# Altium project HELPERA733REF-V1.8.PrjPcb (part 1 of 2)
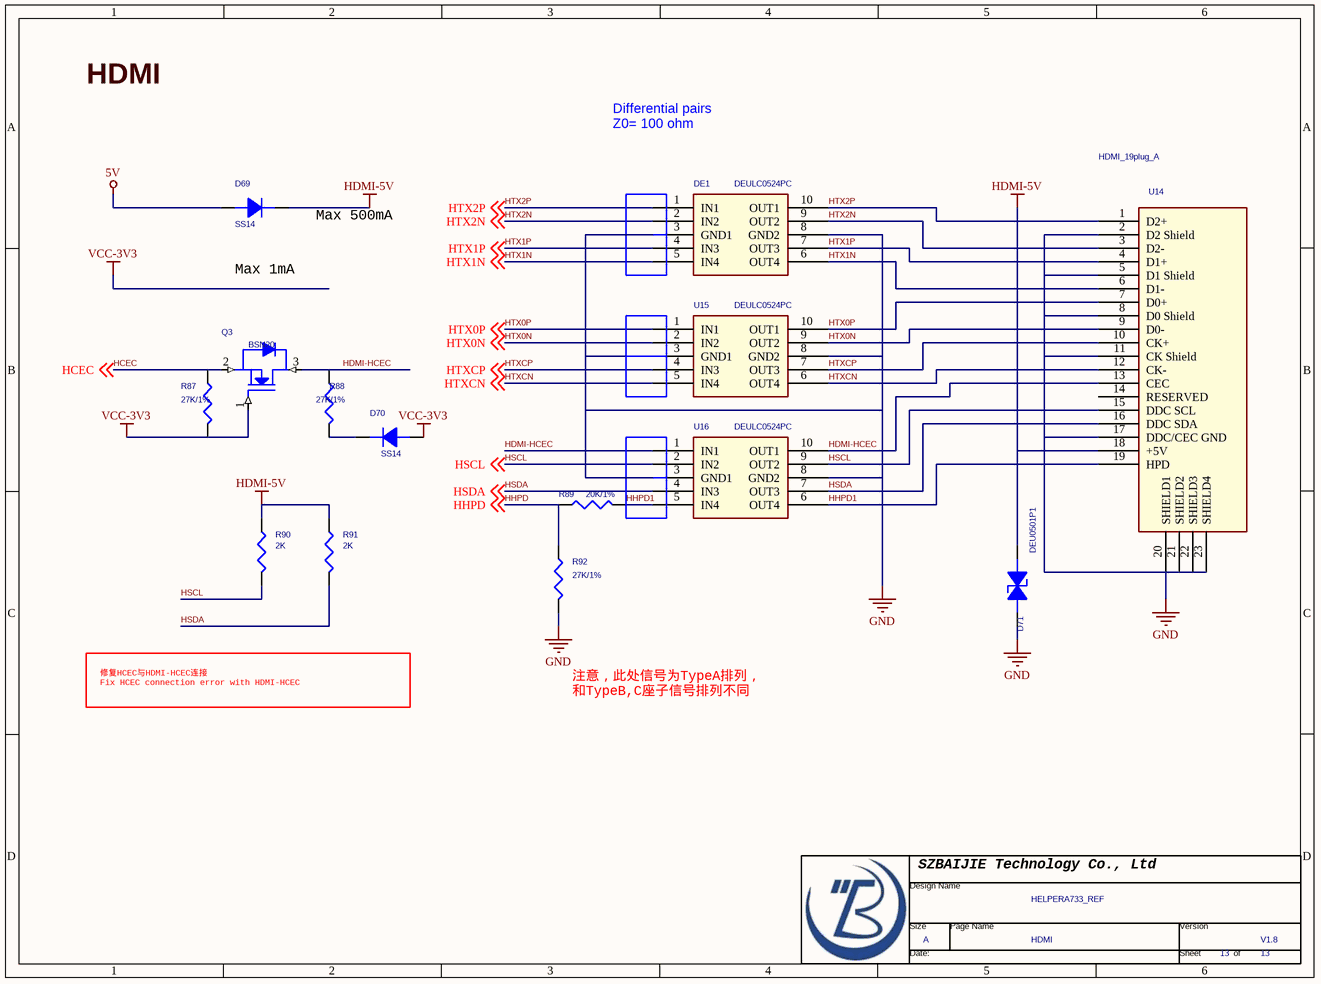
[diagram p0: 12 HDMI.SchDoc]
13 sheets, 488 parts. Net scope: global (net labels, ports and power ports of the same name join across sheets).
Sheets:
  12 HDMI.SchDoc
  11 OTG_host_HUB.SchDoc
  10 Ethernet.SchDoc
  09 IO_ADC_BEEP.SchDoc
  08  UART_485.SchDoc
  07 M.SchDoc
  06 AUDIO AC101_AC101B.SchDoc
  05 TF_KEY_RTC.SchDoc
  04 LCD.SchDoc
  03 CAMERA.SchDoc
  02 Power.SchDoc
  01 CORE.SchDoc
  00 Change log.SchDoc

## Sheet 12 HDMI.SchDoc
size 246 x 182 mm

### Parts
(Parts that share a designator on the sheet are numbered #1, #2 ... from top to bottom, then left to right.)
*#1  Page Count: 13  Page Size: A  Title: HELPERA733_REF  RevCode: V1.8  Doc: HDMI  (hidden comment: TitleBlock0-BJ)  (graphical)
D69  SS14  [SOD123]
D70  SS14  [SOD123]
D71  DEU0501P1  [ESD0402]
DE1  DEULC0524PC  [DFN2510-10_L2.5-W1.0-P0.50-BL]
Q3  BSN20  [sot-23]
R87  27K/1%  [R0402]
R88  27K/1%  [R0402]
R89  20K/1%  [R0402]
R90  2K  [R0402]
R91  2K  [R0402]
R92  27K/1%  [R0402]
U14  HDMI_19plug_A  [HDMIQ]
U15  DEULC0524PC  [DFN2510-10_L2.5-W1.0-P0.50-BL]
U16  DEULC0524PC  [DFN2510-10_L2.5-W1.0-P0.50-BL]

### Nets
5V: D69.1
GND: D71.2(CATHODE) DE1.3(GND1) DE1.8(GND2) R92.2 U14.2(D2_Shield) U14.5(D1_Shield) U14.8(D0_Shield) U14.11(CK_Shield) U14.17(DDC/CEC_GND) U14.20(SHIELD1) U14.21(SHIELD2) U14.22(SHIELD3) U14.23(SHIELD4) U15.3(GND1) U15.8(GND2) U16.3(GND1) U16.8(GND2)
HDMI-5V: D69.2 D71.1(ANODE) R90.2 R91.2 U14.18(+5V)
VCC-3V3: D70.1 Q3.1(GATE) R87.2
HCEC: Q3.2(SOURCE) R87.1 ; off-sheet HCEC
HDMI-HCEC: Q3.3(DRAIN) R88.2 U14.13(CEC) U16.1(IN1) U16.10(OUT1)
HHPD: R89.1 R92.1 ; off-sheet HHPD
HHPD1: R89.2 U14.19(HPD) U16.5(IN4) U16.6(OUT4)
HSCL: R90.1 U14.15(DDC_SCL) U16.2(IN2) U16.9(OUT2) ; off-sheet HSCL
HSDA: R91.1 U14.16(DDC_SDA) U16.4(IN3) U16.7(OUT3) ; off-sheet HSDA
HTX0N: U14.9(D0-) U15.2(IN2) U15.9(OUT2) ; off-sheet HTX0N
HTX0P: U14.7(D0+) U15.1(IN1) U15.10(OUT1) ; off-sheet HTX0P
HTX1N: DE1.5(IN4) DE1.6(OUT4) U14.6(D1-) ; off-sheet HTX1N
HTX1P: DE1.4(IN3) DE1.7(OUT3) U14.4(D1+) ; off-sheet HTX1P
HTX2N: DE1.2(IN2) DE1.9(OUT2) U14.3(D2-) ; off-sheet HTX2N
HTX2P: DE1.1(IN1) DE1.10(OUT1) U14.1(D2+) ; off-sheet HTX2P
HTXCN: U14.12(CK-) U15.5(IN4) U15.6(OUT4) ; off-sheet HTXCN
HTXCP: U14.10(CK+) U15.4(IN3) U15.7(OUT3) ; off-sheet HTXCP
NetD70_2: D70.2 R88.1

Not connected (* = marked no-connect by the designer): U14 14(RESERVED)

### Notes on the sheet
- HDMI
- Differential pairs
  Z0= 100 ohm
- (near D69) Max 500mA
- Max 1mA
- 修复HCEC与HDMI-HCEC连接
  Fix HCEC connection error with HDMI-HCEC
- 注意，此处信号为TypeA排列，
  和TypeB,C座子信号排列不同

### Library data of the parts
D69 D70 = D_0: Allegro PCB Footprint: d2513A
D71 = 1_1.5KE100A: 1ST PART DESCRIPTION: WILL ESD9B5V Bidirection ESD Protection
DE1 U15 U16 = rRClamp0524P
Q3 = NMOS_0
R87 R88 R92 = RESISTOR_Dup4
R89 = R_Dup2
R90 R91 = RESISTOR_Dup3
U14 = HDMI_A

## Sheet 11 OTG_host_HUB.SchDoc
size 386 x 246 mm
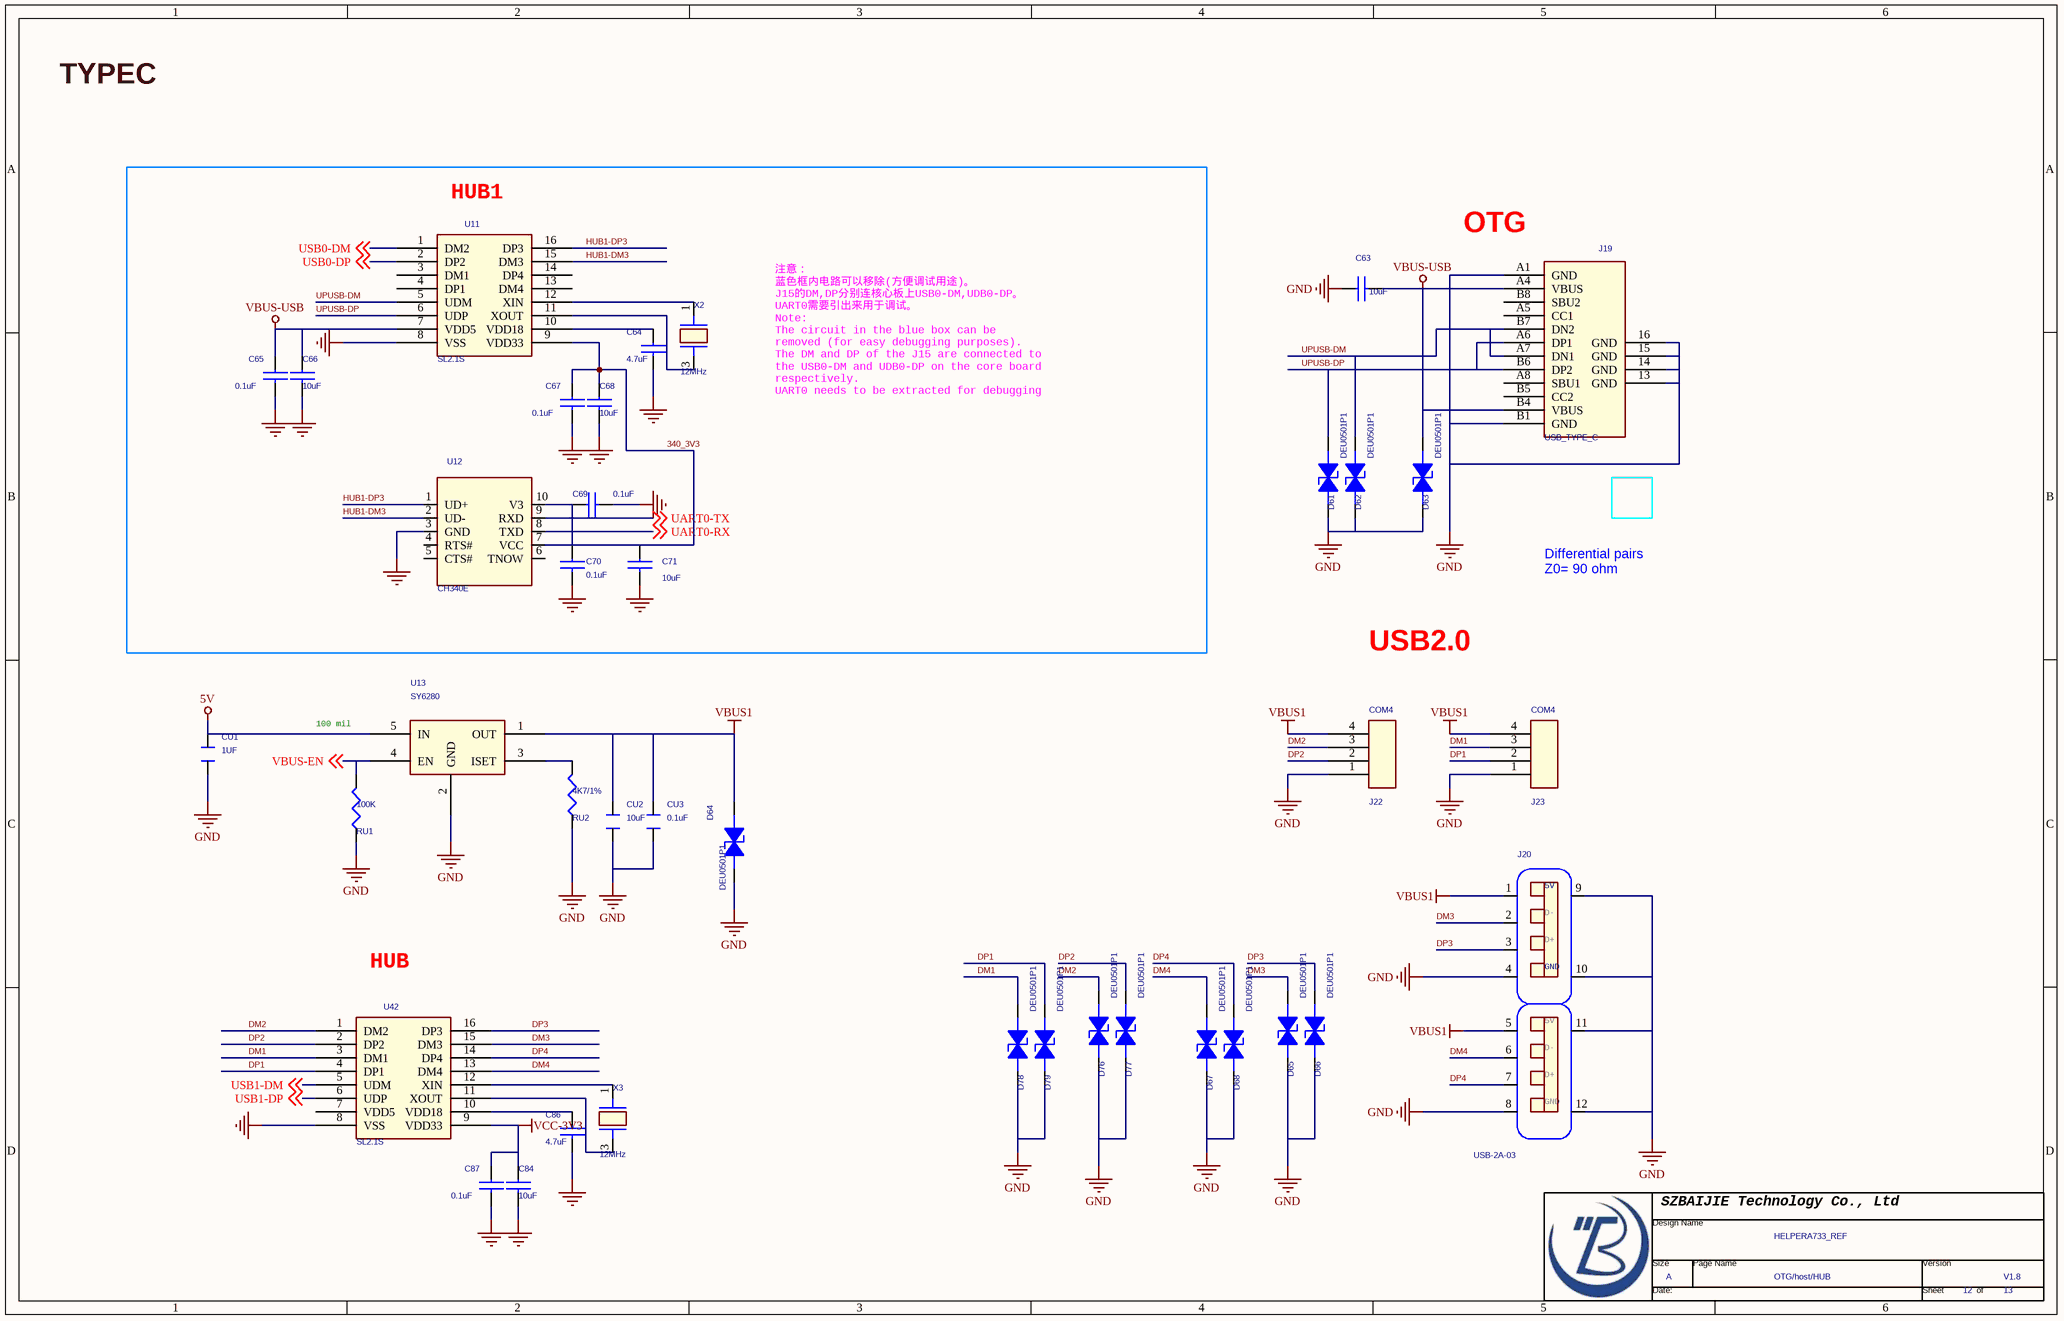
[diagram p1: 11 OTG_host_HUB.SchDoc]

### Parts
(Parts that share a designator on the sheet are numbered #1, #2 ... from top to bottom, then left to right.)
*#2  Page Count: 13  Page Number: 12  Page Size: A  Title: HELPERA733_REF  RevCode: V1.8  Doc: OTG/host/HUB  (hidden comment: TitleBlock0-BJ)  (graphical)
C63  10uF  [C0603]
C64  4.7uF  [C0402]
C65  0.1uF  [C0402]
C66  10uF  [C0603]
C67  0.1uF  [C0402]
C68  10uF  [C0603]
C69  0.1uF  [C0402]
C70  0.1uF  [C0402]
C71  10uF  [C0603]
C84  10uF  [C0603]
C86  4.7uF  [C0402]
C87  0.1uF  [C0402]
CU1  1UF  [C0402]
CU2  10uF  [C0603]
CU3  0.1uF  [C0402]
D61  DEU0501P1  [ESD0402]
D62  DEU0501P1  [ESD0402]
D63  DEU0501P1  [ESD0402]
D64  DEU0501P1  [ESD0402]
D65  DEU0501P1  [ESD0402]
D66  DEU0501P1  [ESD0402]
D67  DEU0501P1  [ESD0402]
D68  DEU0501P1  [ESD0402]
D76  DEU0501P1  [ESD0402]
D77  DEU0501P1  [ESD0402]
D78  DEU0501P1  [ESD0402]
D79  DEU0501P1  [ESD0402]
J19  USB_TYPE_C  [USB_C]
J20  USB-2A-03  [MINI-B]
J22  COM4  [PH-2.0-4P]
J23  COM4  [PH-2.0-4P]
RU1  100K  [R0402]
RU2  4K7/1%  [R0402]
U11  SL2.1S  [SSOP16_SL2.1S]
U12  CH340E  [SO16]
U13  SY6280  [SOP9P1_27B3_90X4_90H1_70]
U42  SL2.1S  [SSOP16_SL2.1S]
X2  12MHz  [XTAL]
X3  12MHz  [XTAL]

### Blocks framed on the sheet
HUB1: C64-C71 U11 U12 X2

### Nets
5V: CU1.2 U13.5(IN)
GND: C63.1 C64.2 C65.2 C66.2 C67.2 C68.2 C69.2 C70.2 C71.2 C84.2 C86.2 C87.2 CU1.1 CU2.1 CU3.1 D61.2(CATHODE) D62.2(CATHODE) D63.2(CATHODE) D64.1(ANODE) D65.2(CATHODE) D66.2(CATHODE) D67.2(CATHODE) D68.2(CATHODE) D76.2(CATHODE) D77.2(CATHODE) D78.2(CATHODE) D79.2(CATHODE) J19.13(GND) J19.14(GND) J19.15(GND) J19.16(GND) J19.A1(GND) J19.B1(GND) J20.4(GND) J20.8(GND) J20.9(S1) J20.10(S2) J20.11(S3) J20.12(S4) J22.1 J23.1 RU1.1 RU2.1 U11.8(VSS) U12.3(GND) U13.2(GND) U42.8(VSS)
VBUS1: CU2.2 CU3.2 D64.2(CATHODE) J20.1(VBUS) J20.5(VBUS) J22.4 J23.4 U13.1(OUT)
VBUS-USB: C63.2 C65.1 C66.1 D63.1(ANODE) J19.A4(VBUS) J19.B4(VBUS) U11.7(VDD5)
VCC-3V3: C84.1 C87.1 U42.9(VDD33)
340_3V3: C67.1 C68.1 C69.1 C70.1 C71.1 U11.9(VDD33) U12.7(VCC) U12.10(V3)
DM1: D78.1(ANODE) J23.3 U42.3(DM1)
DM2: D76.1(ANODE) J22.3 U42.1(DM2)
DM3: D65.1(ANODE) J20.2(D-) U42.15(DM3)
DM4: D67.1(ANODE) J20.6(D-) U42.13(DM4)
DP1: D79.1(ANODE) J23.2 U42.4(DP1)
DP2: D77.1(ANODE) J22.2 U42.2(DP2)
DP3: D66.1(ANODE) J20.3(D+) U42.16(DP3)
DP4: D68.1(ANODE) J20.7(D+) U42.14(DP4)
HUB1-DM3: U11.15(DM3) U12.2(UD-)
HUB1-DP3: U11.16(DP3) U12.1(UD+)
UART0-RX: U12.8(TXD) ; off-sheet UART0-RX
UART0-TX: U12.9(RXD) ; off-sheet UART0-TX
UPUSB-DM: D62.1(ANODE) J19.A7(DN1) J19.B7(DN2) U11.5(UDM)
UPUSB-DP: D61.1(ANODE) J19.A6(DP1) J19.B6(DP2) U11.6(UDP)
USB0-DM: U11.1(DM2) ; off-sheet USB0-DM
USB0-DP: U11.2(DP2) ; off-sheet USB0-DP
USB1-DM: U42.5(UDM) ; off-sheet USB1-DM
USB1-DP: U42.6(UDP) ; off-sheet USB1-DP
VBUS-EN: RU1.2 U13.4(EN) ; off-sheet VBUS-EN
NetC64_1: C64.1 U11.10(VDD18)
NetC86_1: C86.1 U42.10(VDD18)
NetRU2_2: RU2.2 U13.3(ISET)
NetU11_11: U11.11(XOUT) X2.3
NetU11_12: U11.12(XIN) X2.1
NetU42_11: U42.11(XOUT) X3.3
NetU42_12: U42.12(XIN) X3.1

Not connected (* = marked no-connect by the designer): J19 A5(CC1) A8(SBU1) B5(CC2) B8(SBU2); U11 3(DM1) 4(DP1) 13(DM4) 14(DP4); U12 4(RTS#) 5(CTS#) 6(TNOW); U42 7(VDD5)

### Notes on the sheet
- TYPEC
- 注意：
  蓝色框内电路可以移除(方便调试用途)。
  J15的DM,DP分别连核心板上USB0-DM,UDB0-DP。
  UART0需要引出来用于调试。
  Note:
  The circuit in the blue box can be
  removed (for easy debugging purposes).
  The DM and DP of the J15 are connected to
  the USB0-DM and UDB0-DP on the core board
  respectively.
  UART0 needs to be extracted for debugging
- (near J19) OTG
- Differential pairs
  Z0= 90 ohm
- USB2.0
- 100 mil
- HUB

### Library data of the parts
C63 = CAP NP
C64-C68 C84 C86 C87 = CAP NP_Dup1
C69-C71 = CAP NP_Dup2
CU1 = C-C0402: ROOM: EMMC; mypage: 08; PAGE: 2
CU2 = C-C0603_Dup1
CU3 = C-C0402: PAGE: 2; mypage: 08; ROOM: EMMC
D61-D68 D76-D79 = 1_1.5KE100A_Dup1: 1ST PART DESCRIPTION: WILL ESD9B5V Bidirection ESD Protection
J19 = CON12_10
J22 J23 = CON4_0
RU1 = R-R0402-5%_Dup2: mypage: 08; ROOM: EMMC
RU2 = R-R0402-5%_Dup2: ROOM: EMMC; mypage: 08
U11 U42 = MW7220_QFP64_1
U12 = CH340G_1
X2 X3 = XTAL HC49LP 27MHz / MK2743_4: 04 MPN: B18CA1-27.000MHZ; 30 VENDOR: MMD Components; 03 MAN: MMD; 21 FOOTPRINT: HC49 thr. hole d=4.88mm+/-0.2mm; 22 HEIGHT: 3.5mm; 01 IPN: 13-000162-01; 18 SPEED: 27MHz; 20 PACKAGE: HC49; 02 DESC: X-Tal 27.000 MHz 15/30ppm

## Sheet 10 Ethernet.SchDoc
size 386 x 246 mm
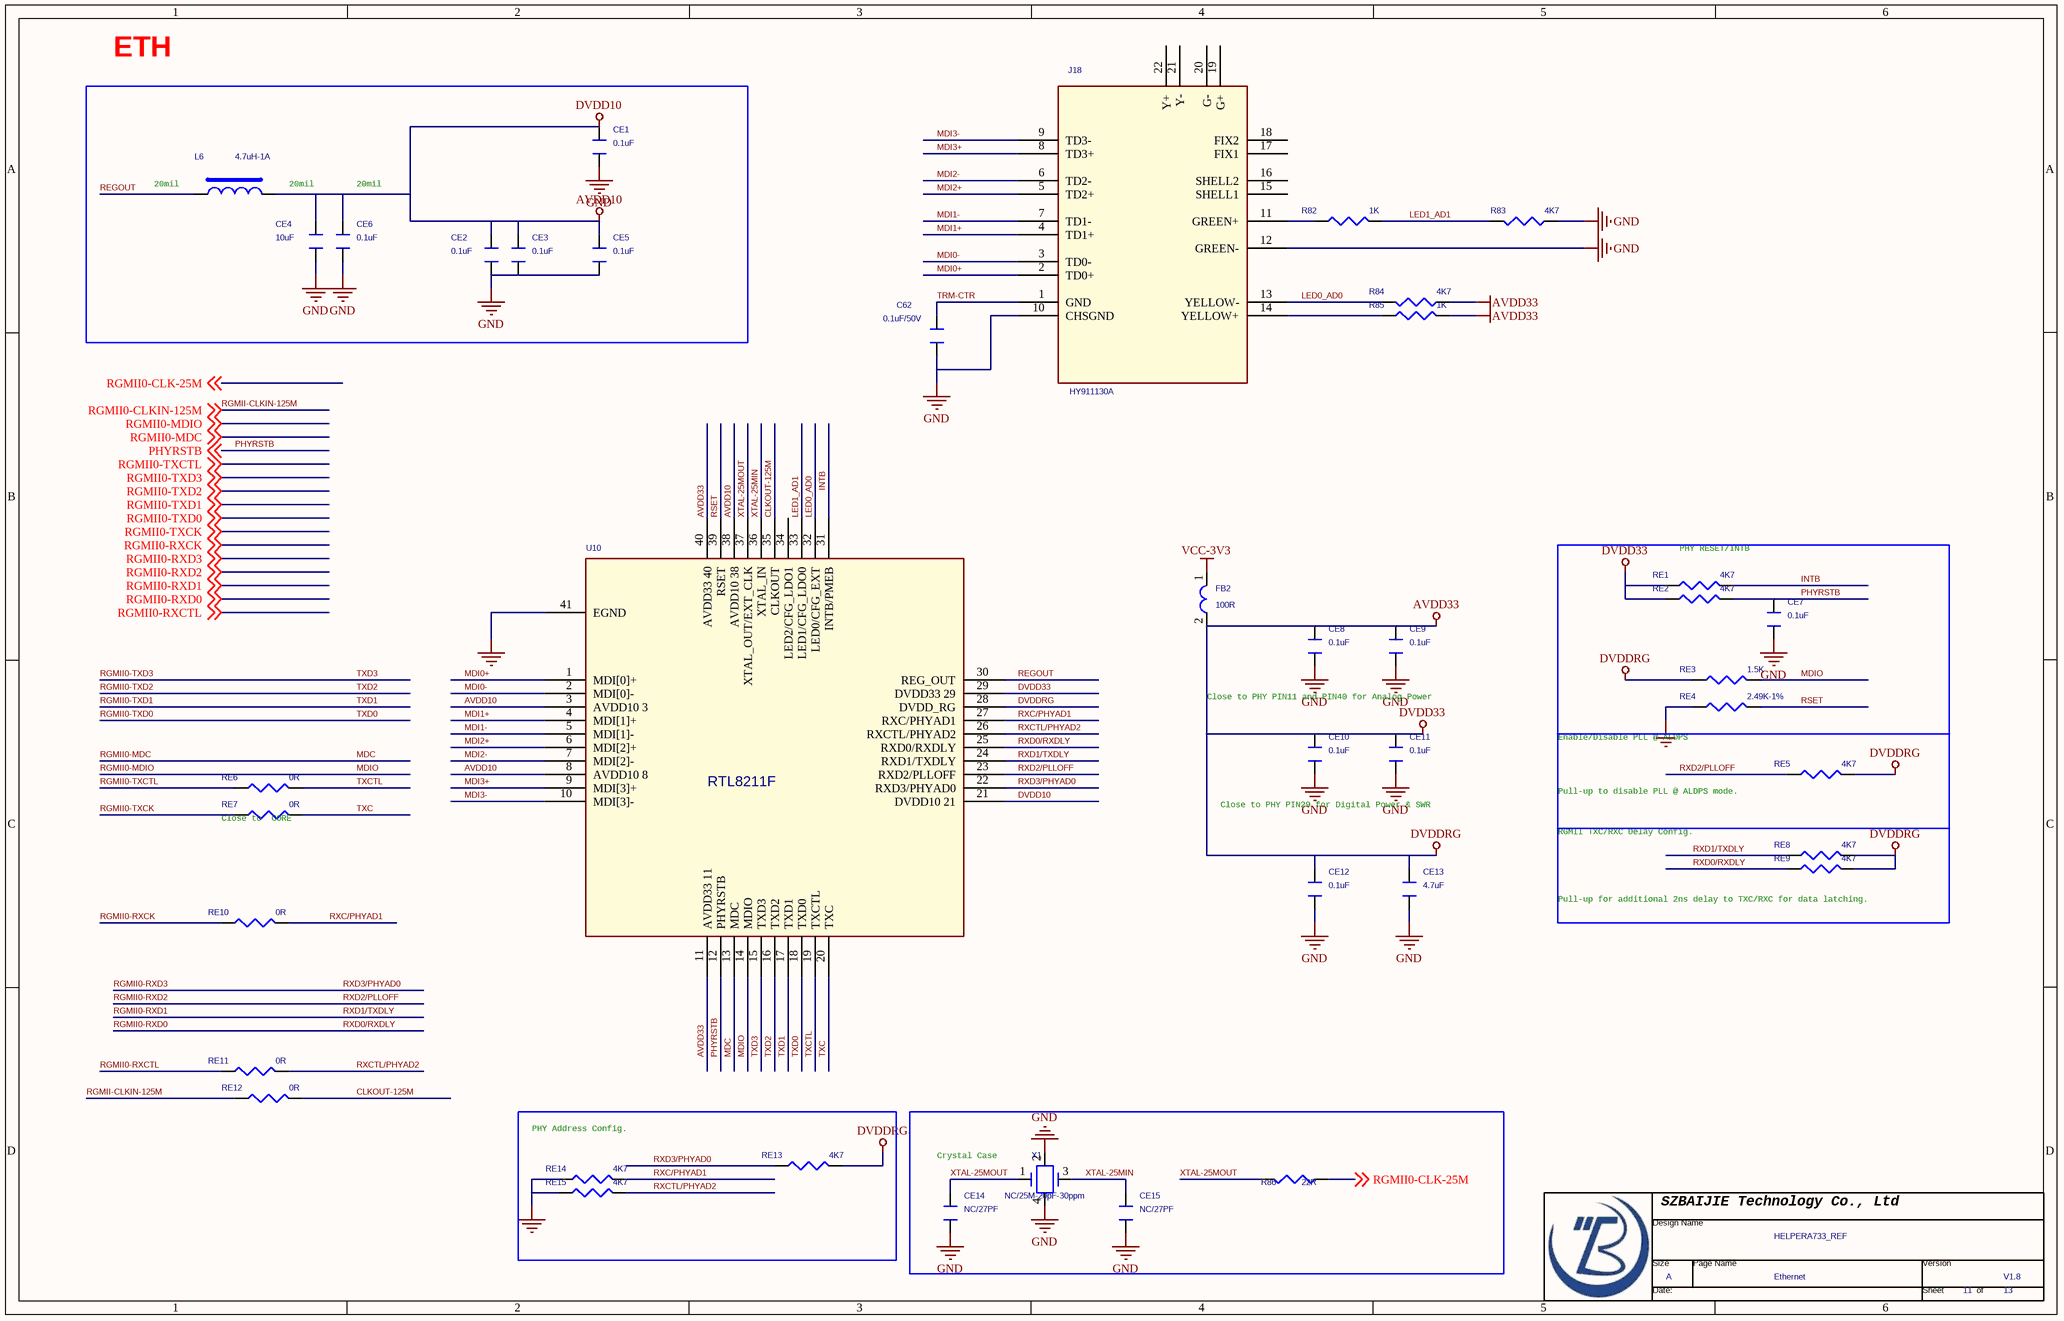
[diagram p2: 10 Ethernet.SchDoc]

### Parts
(Parts that share a designator on the sheet are numbered #1, #2 ... from top to bottom, then left to right.)
*#3  Page Count: 13  Page Number: 11  Page Size: A  Title: HELPERA733_REF  RevCode: V1.8  Doc: Ethernet  (hidden comment: TitleBlock0-BJ)  (graphical)
C62  0.1uF/50V  [C0402]
CE1  0.1uF  [C0402]
CE2  0.1uF  [C0402]
CE3  0.1uF  [C0402]
CE4  10uF  [C0402]
CE5  0.1uF  [C0402]
CE6  0.1uF  [C0402]
CE7  0.1uF  [C0402]
CE8  0.1uF  [C0402]
CE9  0.1uF  [C0402]
CE10  0.1uF  [C0402]
CE11  0.1uF  [C0402]
CE12  0.1uF  [C0402]
CE13  4.7uF  [C0402]
CE14  NC/27PF  [C0402]
CE15  NC/27PF  [C0402]
FB2  100R  [L0603]
J18  HY911130A  [HY911130A]
L6  4.7uH-1A  [LP160_200H100]
R82  1K  [R0402]
R83  4K7  [R0402]
R84  4K7  [R0402]
R85  1K  [R0402]
R86  22R  [R0402]
RE1  4K7  [R0402]
RE2  4K7  [R0402]
RE3  1.5K  [R0402]
RE4  2.49K-1%  [R0402]
RE5  4K7  [R0402]
RE6  0R  [R0402]
RE7  0R  [R0402]
RE8  4K7  [R0402]
RE9  4K7  [R0402]
RE10  0R  [R0402]
RE11  0R  [R0402]
RE12  0R  [R0402]
RE13  4K7  [R0402]
RE14  4K7  [R0402]
RE15  4K7  [R0402]
U10  RTL8211F  [QFN40]
X1  NC/25M-20pF-30ppm  [X3225]

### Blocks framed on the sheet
PHY RESET/INTB: CE7 RE1-RE4
RGMII TXC/RXC Delay Config.: RE8 RE9
PHY Address Config.: RE13-RE15
Crystal Case: CE14 CE15 R86 X1

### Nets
AVDD10: CE1.2 CE2.2 CE3.2 CE4.2 CE5.2 CE6.2 L6.2 U10.3(AVDD10_3) U10.8(AVDD10_8) U10.21(DVDD10_21) U10.38(AVDD10_38)  [also labelled DVDD10]
AVDD33: CE8.2 CE9.2 CE10.2 CE11.2 CE12.2 CE13.2 FB2.2 R84.1 R85.2 RE1.1 RE2.1 RE3.1 RE5.2 RE8.2 RE9.2 RE13.2 U10.11(AVDD33_11) U10.28(DVDD_RG) U10.29(DVDD33_29) U10.40(AVDD33_40)  [also labelled DVDD33, DVDDRG]
GND: C62.1 CE1.1 CE2.1 CE3.1 CE4.1 CE5.1 CE6.1 CE7.1 CE8.1 CE9.1 CE10.1 CE11.1 CE12.1 CE13.1 CE14.1 CE15.1 J18.10(CHSGND) J18.12(GREEN-) R83.1 RE4.1 RE14.1 RE15.1 U10.41(EGND) X1.2 X1.4
VCC-3V3: FB2.1
CLKOUT-125M: RE12.2 U10.35(CLKOUT)
INTB: RE1.2 U10.31(INTB/PMEB)
LED0_AD0: J18.13(YELLOW-) R84.2 U10.32(LED0/CFG_EXT)
LED1_AD1: R82.2 R83.2 U10.33(LED1/CFG_LDO0)
MDC: U10.13(MDC) ; off-sheet RGMII0-MDC  [also labelled RGMII0-MDC]
MDI0+: J18.2(TD0+) U10.1(MDI[0]+)
MDI0-: J18.3(TD0-) U10.2(MDI[0]-)
MDI1+: J18.4(TD1+) U10.4(MDI[1]+)
MDI1-: J18.7(TD1-) U10.5(MDI[1]-)
MDI2+: J18.5(TD2+) U10.6(MDI[2]+)
MDI2-: J18.6(TD2-) U10.7(MDI[2]-)
MDI3+: J18.8(TD3+) U10.9(MDI[3]+)
MDI3-: J18.9(TD3-) U10.10(MDI[3]-)
MDIO: RE3.2 U10.14(MDIO) ; off-sheet RGMII0-MDIO  [also labelled RGMII0-MDIO]
PHYRSTB: CE7.2 RE2.2 U10.12(PHYRSTB) ; off-sheet PHYRSTB
REGOUT: L6.1 U10.30(REG_OUT)
RGMII0-CLK-25M: R86.1 ; off-sheet RGMII0-CLK-25M
RGMII0-RXCK: RE10.1 ; off-sheet RGMII0-RXCK
RGMII0-RXCTL: RE11.1 ; off-sheet RGMII0-RXCTL
RGMII0-RXD0: RE9.1 U10.25(RXD0/RXDLY) ; off-sheet RGMII0-RXD0  [also labelled RXD0/RXDLY]
RGMII0-RXD1: RE8.1 U10.24(RXD1/TXDLY) ; off-sheet RGMII0-RXD1  [also labelled RXD1/TXDLY]
RGMII0-RXD2: RE5.1 U10.23(RXD2/PLLOFF) ; off-sheet RGMII0-RXD2  [also labelled RXD2/PLLOFF]
RGMII0-RXD3: RE13.1 U10.22(RXD3/PHYAD0) ; off-sheet RGMII0-RXD3  [also labelled RXD3/PHYAD0]
RGMII0-TXCK: RE7.1 ; off-sheet RGMII0-TXCK
RGMII0-TXCTL: RE6.1 ; off-sheet RGMII0-TXCTL
RGMII0-TXD0: U10.18(TXD0) ; off-sheet RGMII0-TXD0  [also labelled TXD0]
RGMII0-TXD1: U10.17(TXD1) ; off-sheet RGMII0-TXD1  [also labelled TXD1]
RGMII0-TXD2: U10.16(TXD2) ; off-sheet RGMII0-TXD2  [also labelled TXD2]
RGMII0-TXD3: U10.15(TXD3) ; off-sheet RGMII0-TXD3  [also labelled TXD3]
RGMII-CLKIN-125M: RE12.1 ; off-sheet RGMII0-CLKIN-125M  [also labelled RGMII0-CLKIN-125M]
RSET: RE4.2 U10.39(RSET)
RXC/PHYAD1: RE10.2 RE14.2 U10.27(RXC/PHYAD1)
RXCTL/PHYAD2: RE11.2 RE15.2 U10.26(RXCTL/PHYAD2)
TRM-CTR: C62.2 J18.1(GND)
TXC: RE7.2 U10.20(TXC)
TXCTL: RE6.2 U10.19(TXCTL)
XTAL-25MIN: CE15.2 U10.36(XTAL_IN) X1.3
XTAL-25MOUT: CE14.2 R86.2 U10.37(XTAL_OUT/EXT_CLK) X1.1
NetJ18_11: J18.11(GREEN+) R82.1
NetJ18_14: J18.14(YELLOW+) R85.1

Not connected (* = marked no-connect by the designer): J18 15(SHELL1) 16(SHELL2) 17(FIX1) 18(FIX2) 19(G+) 20(G-) 21(Y-) 22(Y+); U10 34(LED2/CFG_LDO1)

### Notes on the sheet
- ETH
- (near L6) 20mil
- 20mil
- Close to PHY PIN11 and PIN40 for Analog Power
- Pull-up to disable PLL @ ALDPS mode.
- Enable/Disable PLL @ ALDPS
- (near RE7) Close to  CORE
- Close to PHY PIN29 for Digital Power & SWR
- Pull-up for additional 2ns delay to TXC/RXC for data latching.

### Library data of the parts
C62 = CAPACITOR_0_Dup1
CE1-CE15 = C-C0402_Dup2
FB2 = INDUCTOR_0_Dup1: RoHS BEAD/600ohm 100Mhz Z=600Ω DCR<0.2Ω 800mA SMT L0603; OriginalSymbolOrigin: (10,0); Pin Names Rotate: TRUE; Pin Names Visible: FALSE
L6 = L-L2016
R82-R86 = R_Dup6
RE1-RE15 = R-R0402-5%_Dup4
U10 = 8211F: ID: OT-IC0192
X1 = 3224: ID: CR-S-P0019

## Sheet 09 IO_ADC_BEEP.SchDoc
size 246 x 182 mm
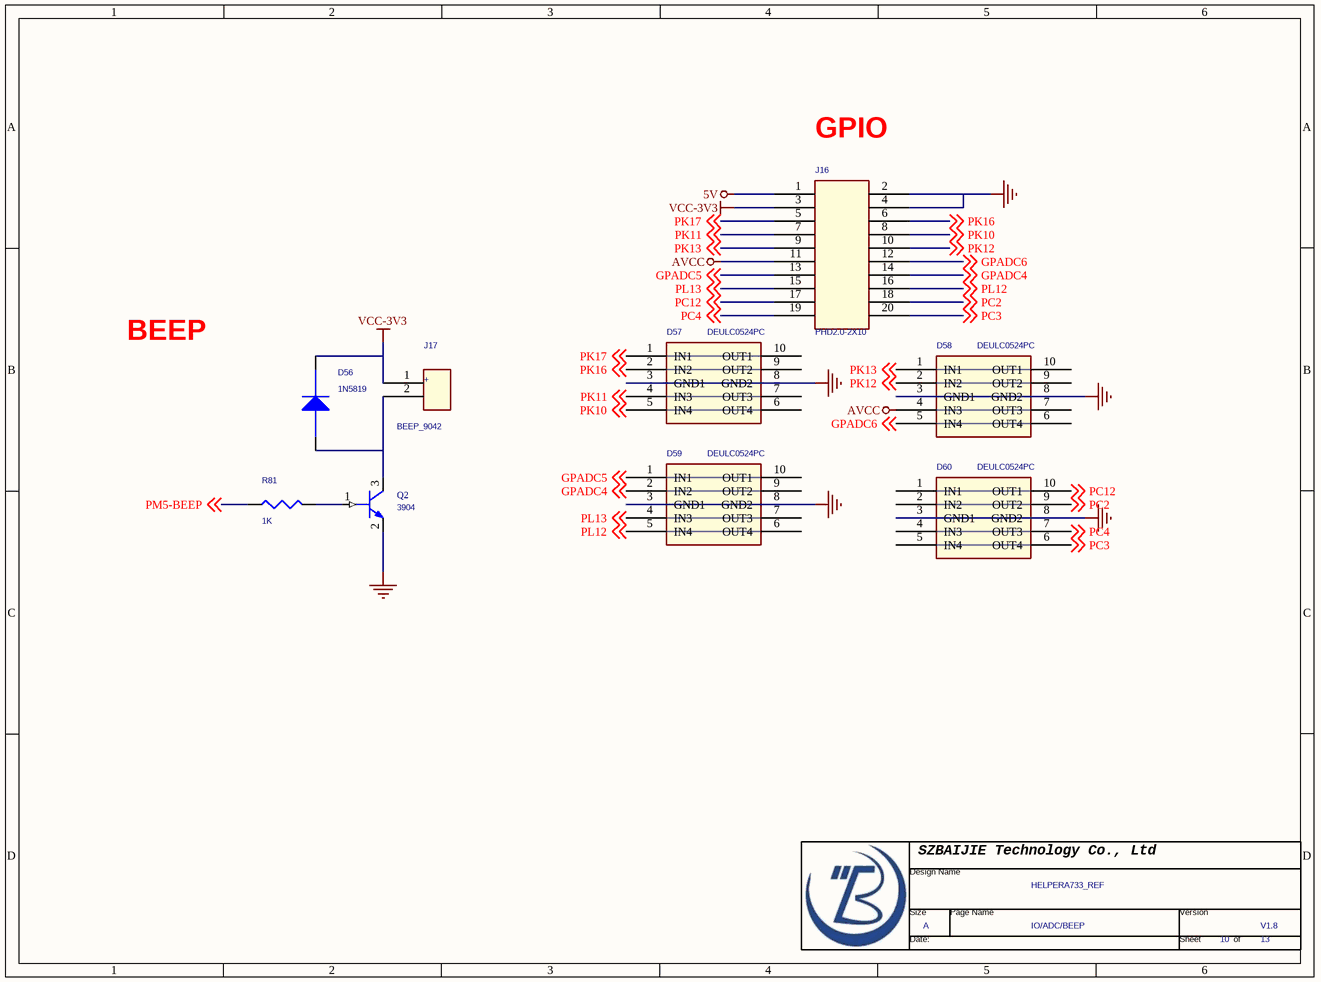
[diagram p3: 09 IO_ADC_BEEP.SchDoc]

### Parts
(Parts that share a designator on the sheet are numbered #1, #2 ... from top to bottom, then left to right.)
*#4  Page Count: 13  Page Number: 10  Page Size: A  Title: HELPERA733_REF  RevCode: V1.8  Doc: IO/ADC/BEEP  (hidden comment: TitleBlock0-BJ)  (graphical)
D56  1N5819  [SOD323]
D57  DEULC0524PC  [DFN2510-10_L2.5-W1.0-P0.50-BL]
D58  DEULC0524PC  [DFN2510-10_L2.5-W1.0-P0.50-BL]
D59  DEULC0524PC  [DFN2510-10_L2.5-W1.0-P0.50-BL]
D60  DEULC0524PC  [DFN2510-10_L2.5-W1.0-P0.50-BL]
J16  PHD2.0-2X10  [PHD2.0-2X10]
J17  BEEP_9042  [BEEP_9042]
Q2  3904  [SOT23]
R81  1K  [R0402]

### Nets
5V: J16.1
AVCC: D58.4(IN3) D58.7(OUT3) J16.11
GND: D57.3(GND1) D57.8(GND2) D58.3(GND1) D58.8(GND2) D59.3(GND1) D59.8(GND2) D60.3(GND1) D60.8(GND2) J16.2 J16.4 Q2.2(EMITTER)
VCC-3V3: D56.2(CATHODE) J16.3 J17.1
GPADC4: D59.2(IN2) D59.9(OUT2) J16.14 ; off-sheet GPADC4
GPADC5: D59.1(IN1) D59.10(OUT1) J16.13 ; off-sheet GPADC5
GPADC6: D58.5(IN4) D58.6(OUT4) J16.12 ; off-sheet GPADC6
PC2: D60.2(IN2) D60.9(OUT2) J16.18 ; off-sheet PC2
PC3: D60.5(IN4) D60.6(OUT4) J16.20 ; off-sheet PC3
PC4: D60.4(IN3) D60.7(OUT3) J16.19 ; off-sheet PC4
PC12: D60.1(IN1) D60.10(OUT1) J16.17 ; off-sheet PC12
PK10: D57.5(IN4) D57.6(OUT4) J16.8 ; off-sheet PK10
PK11: D57.4(IN3) D57.7(OUT3) J16.7 ; off-sheet PK11
PK12: D58.2(IN2) D58.9(OUT2) J16.10 ; off-sheet PK12
PK13: D58.1(IN1) D58.10(OUT1) J16.9 ; off-sheet PK13
PK16: D57.2(IN2) D57.9(OUT2) J16.6 ; off-sheet PK16
PK17: D57.1(IN1) D57.10(OUT1) J16.5 ; off-sheet PK17
PL12: D59.5(IN4) D59.6(OUT4) J16.16 ; off-sheet PL12
PL13: D59.4(IN3) D59.7(OUT3) J16.15 ; off-sheet PL13
PM5-BEEP: R81.1 ; off-sheet PM5-BEEP
NetD56_1: D56.1(ANODE) J17.2 Q2.3(COLLECTOR)
NetQ2_1: Q2.1(BASE) R81.2

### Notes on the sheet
- (near J16) GPIO
- BEEP

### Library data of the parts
D56 = BAS21/SOT_1
D57-D60 = rRClamp0524P
J16 = CON24A_3
J17 = CON2_0_Dup1
Q2 = 2N3904_0
R81 = R_Dup4

## Sheet 08  UART_485.SchDoc
size 246 x 182 mm
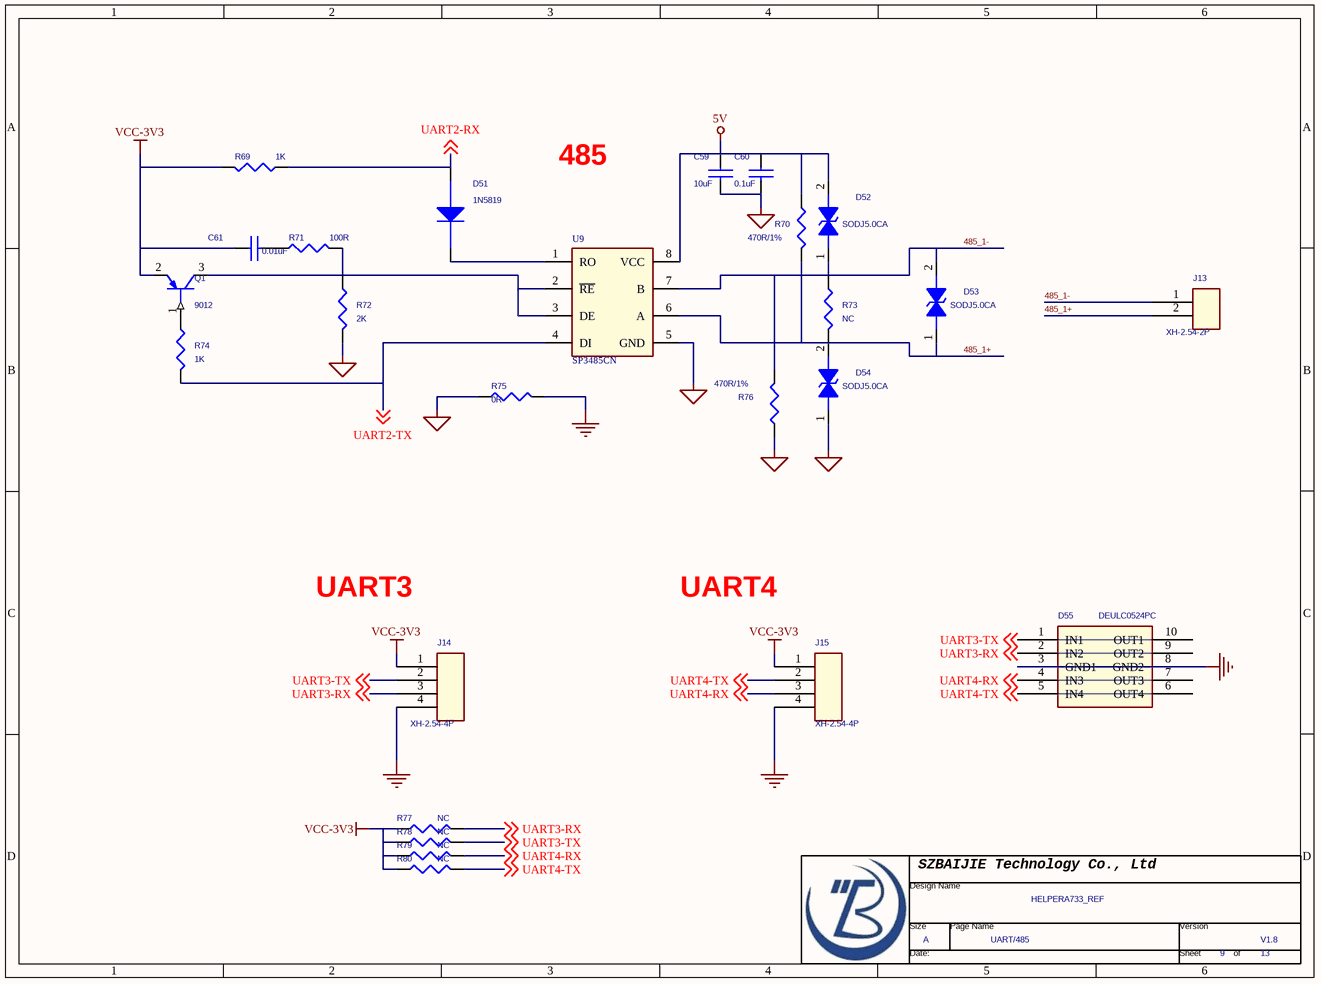
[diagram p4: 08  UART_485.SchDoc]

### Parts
(Parts that share a designator on the sheet are numbered #1, #2 ... from top to bottom, then left to right.)
*#5  Page Count: 13  Page Number: 9  Page Size: A  Title: HELPERA733_REF  RevCode: V1.8  Doc: UART/485  (hidden comment: TitleBlock0-BJ)  (graphical)
C59  10uF  [C0603]
C60  0.1uF  [C0402]
C61  0.01uF  [C0402]
D51  1N5819  [SOD323]
D52  SODJ5.0CA  [R0402]
D53  SODJ5.0CA  [R0402]
D54  SODJ5.0CA  [R0402]
D55  DEULC0524PC  [DFN2510-10_L2.5-W1.0-P0.50-BL]
J13  XH-2.54-2P  [XH-2.54-2P]
J14  XH-2.54-4P  [XH-2.54-4P]
J15  XH-2.54-4P  [XH-2.54-4P]
Q1  9012  [SOT23]
R69  1K  [R0402]
R70  470R/1%  [R0402]
R71  100R  [R0402]
R72  2K  [R0402]
R73  NC  [R0402]
R74  1K  [R0402]
R75  0R  [R0402]
R76  470R/1%  [R0402]
R77  NC  [R0402]
R78  NC  [R0402]
R79  NC  [R0402]
R80  NC  [R0402]
U9  SP3485CN  [SO8]

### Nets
5V: C59.1 C60.1 D52.2(CATHODE) R70.1 U9.8(VCC)
GND: D55.3(GND1) D55.8(GND2) J14.4 J15.4 R75.2
GND_485: C59.2 C60.2 D54.1(ANODE) R72.2 R75.1 R76.1 U9.5(GND)
VCC-3V3: C61.1 J14.1 J15.1 Q1.2(EMITTER) R69.2 R77.1 R78.1 R79.1 R80.1
485_1+: D53.1(ANODE) D54.2(CATHODE) J13.2 R70.2 R73.2 U9.6(A)
485_1-: D52.1(ANODE) D53.2(CATHODE) J13.1 R73.1 R76.2 U9.7(B)
UART2-RX: D51.1(ANODE) R69.1 ; off-sheet UART2-RX
UART2-TX: R74.2 U9.4(DI) ; off-sheet UART2-TX
UART3-RX: D55.2(IN2) D55.9(OUT2) J14.3 R77.2 ; off-sheet UART3-RX
UART3-TX: D55.1(IN1) D55.10(OUT1) J14.2 R78.2 ; off-sheet UART3-TX
UART4-RX: D55.4(IN3) D55.7(OUT3) J15.3 R79.2 ; off-sheet UART4-RX
UART4-TX: D55.5(IN4) D55.6(OUT4) J15.2 R80.2 ; off-sheet UART4-TX
NetC61_2: C61.2 R71.1
NetD51_2: D51.2(CATHODE) U9.1(RO)
NetQ1_1: Q1.1(BASE) R74.1
NetQ1_3: Q1.3(COLLECTOR) R71.2 R72.1 U9.2(~{RE}) U9.3(DE)

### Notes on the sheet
- 485
- UART3
- UART4

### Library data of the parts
C59 = C0603
C60 C61 = C0402
D51 = BAS21/SOT_1
D52-D54 = ESD_DIODE: TVS diode;DC Working Voltage(VDC):16.0V;Clamping Voltage(VCL)Ipeak = 1A,8/20s:290V Maximum;Capacitance(C)@1MHz, 1V:2pF Typic; Part Name: CDS2C16GTH; Brand: EPCOS稲炊吹
D55 = rRClamp0524P
J13 = CON4_3_Dup1
J14 J15 = CON4
Q1 = 2N3906_0
R69-R80 = R0402
U9 = SP3485

## Sheet 07 M.SchDoc
size 386 x 246 mm
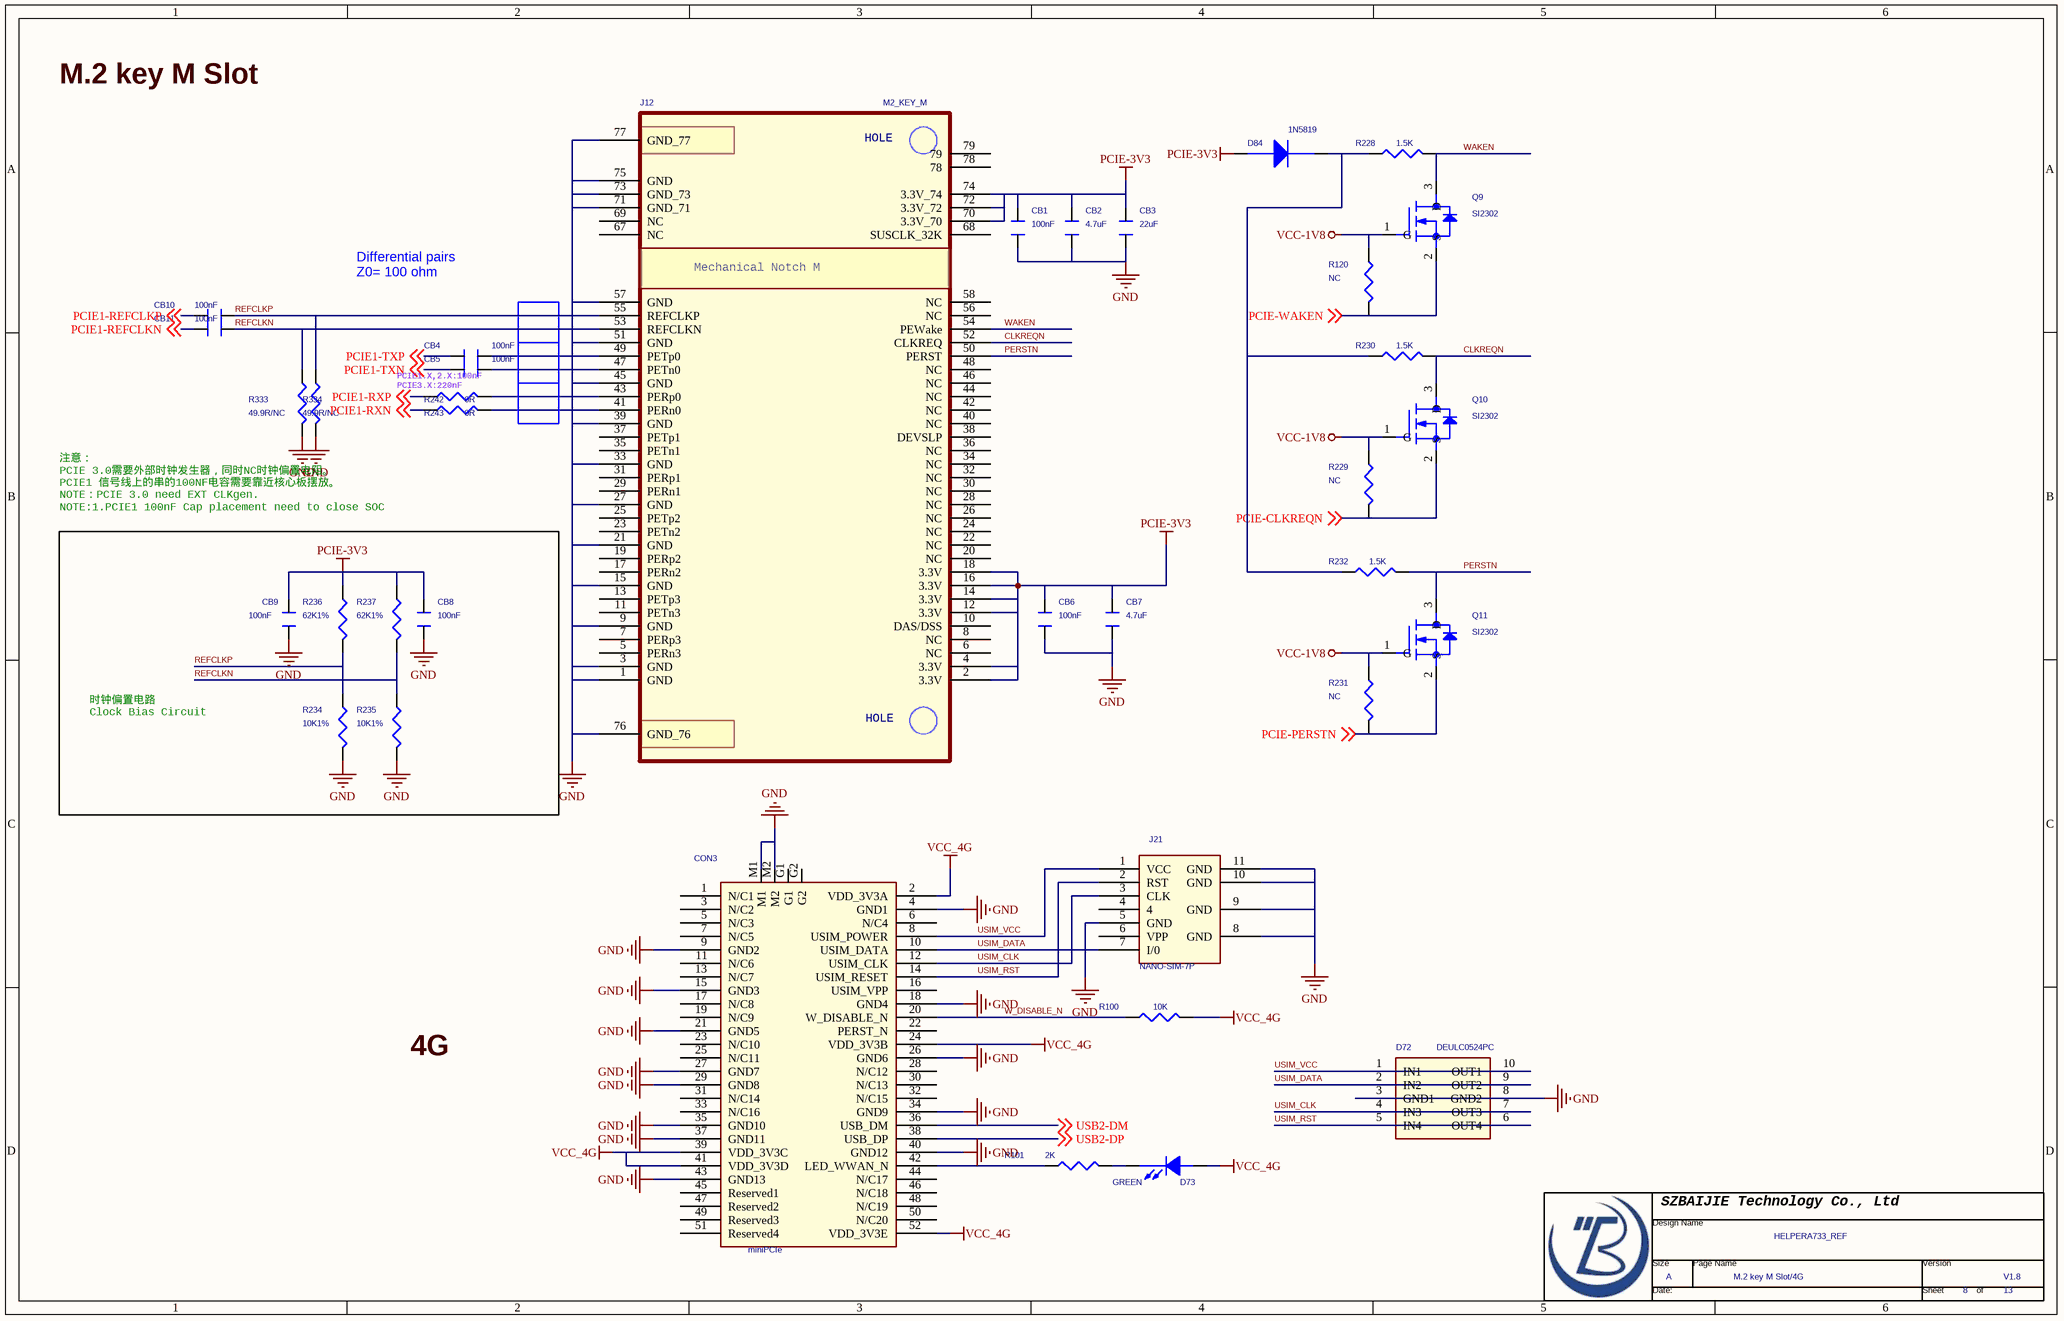
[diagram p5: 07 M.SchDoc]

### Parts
(Parts that share a designator on the sheet are numbered #1, #2 ... from top to bottom, then left to right.)
*#6  Page Count: 13  Page Number: 8  Page Size: A  Title: HELPERA733_REF  RevCode: V1.8  Doc: M.2 key M Slot/4G  (hidden comment: TitleBlock0-BJ)  (graphical)
CB1  100nF  [C0402]
CB2  4.7uF  [C0402]
CB3  22uF  [C0805]
CB4  100nF  [C0402]
CB5  100nF  [C0402]
CB6  100nF  [C0402]
CB7  4.7uF  [C0402]
CB8  100nF  [C0402]
CB9  100nF  [C0402]
CB10  100nF  [C0402]
CB11  100nF  [C0402]
CON3  miniPCIe  [MINI_PCIEX1-52P-5.2H]
D72  DEULC0524PC  [DFN2510-10_L2.5-W1.0-P0.50-BL]
D73  GREEN  [D0603]
D84  1N5819  [SOD323]
J12  M2_KEY_M  [M2_KEY_B_M]
J21  NANO-SIM-7P  [NANO-SIM-7P]
Q9  SI2302  [SOT3P95B130_290H103]
Q10  SI2302  [SOT3P95B130_290H103]
Q11  SI2302  [SOT3P95B130_290H103]
R100  10K  [R0402]
R101  2K  [R0402]
R120  NC  [R0402]
R228  1.5K  [R0402]
R229  NC  [R0402]
R230  1.5K  [R0402]
R231  NC  [R0402]
R232  1.5K  [R0402]
R234  10K1%  [R0402]
R235  10K1%  [R0402]
R236  62K1%  [R0402]
R237  62K1%  [R0402]
R242  0R  [R0402]
R243  0R  [R0402]
R333  49.9R/NC  [R0402]
R334  49.9R/NC  [R0402]

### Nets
GND: CB1.1 CB2.1 CB3.1 CB6.1 CB7.1 CB8.1 CB9.1 CON3.4(GND1) CON3.9(GND2) CON3.15(GND3) CON3.18(GND4) CON3.21(GND5) CON3.26(GND6) CON3.27(GND7) CON3.29(GND8) CON3.34(GND9) CON3.35(GND10) CON3.37(GND11) CON3.40(GND12) CON3.43(GND13) CON3.M1 CON3.M2 D72.3(GND1) D72.8(GND2) J12.1(GND) J12.3(GND) J12.9(GND) J12.15(GND) J12.21(GND) J12.27(GND) J12.33(GND) J12.39(GND) J12.45(GND) J12.51(GND) J12.57(GND) J12.71(GND_71) J12.73(GND_73) J12.75(GND) J12.76(GND_76) J12.77(GND_77) J21.5(GND) J21.8(GND) J21.9(GND) J21.10(GND) J21.11(GND) R234.2 R235.2 R333.2 R334.2
PCIE-3V3: CB1.2 CB2.2 CB3.2 CB6.2 CB7.2 CB8.2 CB9.2 D84.1(ANODE) J12.2(3.3V) J12.4(3.3V) J12.12(3.3V) J12.14(3.3V) J12.16(3.3V) J12.18(3.3V) J12.70(3.3V_70) J12.72(3.3V_72) J12.74(3.3V_74) R236.1 R237.1
VCC-1V8: Q9.1(G) Q10.1(G) Q11.1(G) R120.1 R229.1 R231.1
VCC_4G: CON3.2(VDD_3V3A) CON3.24(VDD_3V3B) CON3.39(VDD_3V3C) CON3.41(VDD_3V3D) CON3.52(VDD_3V3E) D73.1(ANODE) R100.2
CLKREQN: J12.52(CLKREQ) Q10.3(D) R230.2
PCIE1-REFCLKN: CB11.1 ; off-sheet PCIE1-REFCLKN
PCIE1-REFCLKP: CB10.1 ; off-sheet PCIE1-REFCLKP
PCIE1-RXN: R243.1 ; off-sheet PCIE1-RXN
PCIE1-RXP: R242.1 ; off-sheet PCIE1-RXP
PCIE1-TXN: CB5.1 ; off-sheet PCIE1-TXN
PCIE1-TXP: CB4.1 ; off-sheet PCIE1-TXP
PCIE-CLKREQN: Q10.2(S) R229.2 ; off-sheet PCIE-CLKREQN
PCIE-PERSTN: Q11.2(S) R231.2 ; off-sheet PCIE-PERSTN
PCIE-WAKEN: Q9.2(S) R120.2 ; off-sheet PCIE-WAKEN
PERSTN: J12.50(PERST) Q11.3(D) R232.2
REFCLKN: CB11.2 J12.53(REFCLKN) R235.1 R237.2 R333.1
REFCLKP: CB10.2 J12.55(REFCLKP) R234.1 R236.2 R334.1
USB2-DM: CON3.36(USB_DM) ; off-sheet USB2-DM
USB2-DP: CON3.38(USB_DP) ; off-sheet USB2-DP
USIM_CLK: CON3.12(USIM_CLK) D72.4(IN3) D72.7(OUT3) J21.3(CLK)
USIM_DATA: CON3.10(USIM_DATA) D72.2(IN2) D72.9(OUT2) J21.7(I/0)
USIM_RST: CON3.14(USIM_RESET) D72.5(IN4) D72.6(OUT4) J21.2(RST)
USIM_VCC: CON3.8(USIM_POWER) D72.1(IN1) D72.10(OUT1) J21.1(VCC)
W_DISABLE_N: CON3.20(W_DISABLE_N) R100.1
WAKEN: J12.54(PEWake) Q9.3(D) R228.2
NetCB4_2: CB4.2 J12.49(PETp0)
NetCB5_2: CB5.2 J12.47(PETn0)
NetCON3_42: CON3.42(LED_WWAN_N) R101.1
NetD73_2: D73.2(CATHODE) R101.2
NetD84_2: D84.2(CATHODE) R228.1 R230.1 R232.1
NetJ12_41: J12.41(PERn0) R243.2
NetJ12_43: J12.43(PERp0) R242.2

Not connected (* = marked no-connect by the designer): CON3 1(N/C1) 3(N/C2) 5(N/C3) 6(N/C4) 7(N/C5) 11(N/C6) 13(N/C7) 16(USIM_VPP) 17(N/C8) 19(N/C9) 22(PERST_N) 23(N/C10) 25(N/C11) 28(N/C12) 30(N/C13) 31(N/C14) 32(N/C15) 33(N/C16) 44(N/C17) 45(Reserved1) 46(N/C18) 47(Reserved2) 48(N/C19) 49(Reserved3) 50(N/C20) 51(Reserved4) G1 G2; J12 5(PERn3) 6(NC) 7(PERp3) 8(NC) 10(DAS/DSS) 11(PETn3) 13(PETp3) 17(PERn2) 19(PERp2) 20(NC) 22(NC) 23(PETn2) 24(NC) 25(PETp2) 26(NC) 28(NC) 29(PERn1) 30(NC) 31(PERp1) 32(NC) 34(NC) 35(PETn1) 36(NC) 37(PETp1) 38(DEVSLP) 40(NC) 42(NC) 44(NC) 46(NC) 48(NC) 56(NC) 58(NC) 67(NC) 68(SUSCLK_32K) 69(NC) 78 79; J21 4 6(VPP)

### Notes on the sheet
- M.2 key M Slot
- Differential pairs
  Z0= 100 ohm
- PCIE1.X,2.X:100nF
  PCIE3.X:220nF
- 注意：
  PCIE 3.0需要外部时钟发生器，同时NC时钟偏置电阻。
  PCIE1 信号线上的串的100NF电容需要靠近核心板摆放。
  NOTE：PCIE 3.0 need EXT CLKgen.
  NOTE:1.PCIE1 100nF Cap placement need to close SOC
- 时钟偏置电路
  Clock Bias Circuit
- 4G

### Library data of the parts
CB1 CB6 CB10 CB11 = CAPACITOR_0_Dup1: PAGE: 2; ROOM: LVDS
CB2-CB5 CB7-CB9 = CAPACITOR_0_Dup1: ROOM: LVDS; PAGE: 2
CON3 = CON50A_5
D72 = rRClamp0524P
D73 = LED
D84 = BAS21/SOT_1
J12 = M2_KEY_B_0
J21 = SIM-7P_0
Q9-Q11 = NMOS-2N7002: ID: MOS0002; Parameter: SOT23
R100 R101 = R_Dup6
R120 R228-R232 R234-R237 R242 R243 R333 R334 = R_Dup5

## Sheet 06 AUDIO AC101_AC101B.SchDoc
size 513 x 386 mm
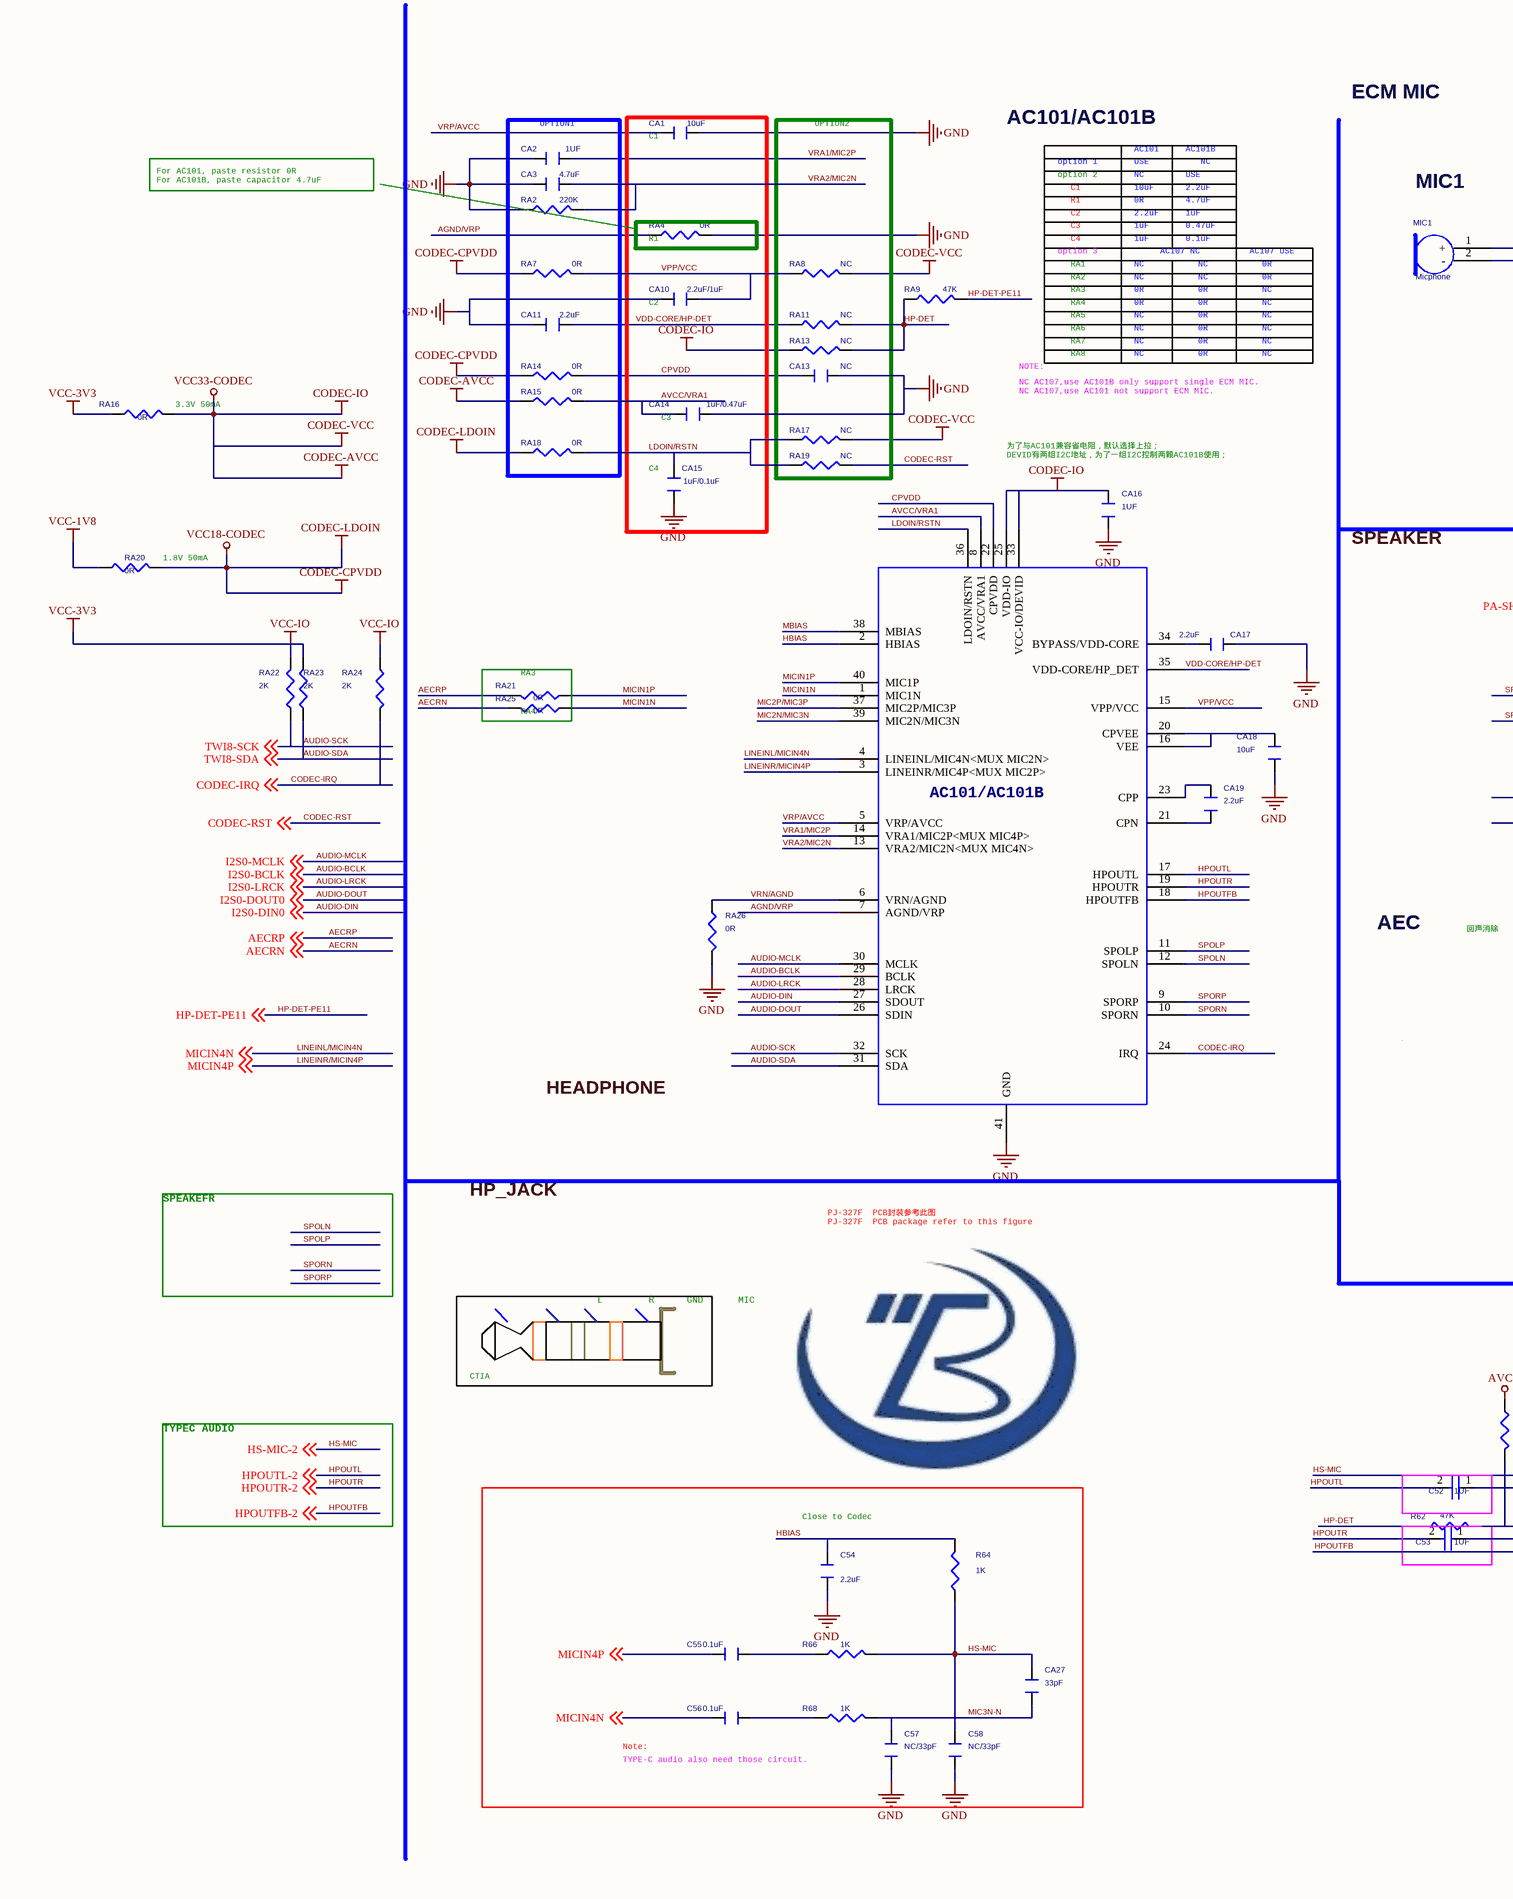
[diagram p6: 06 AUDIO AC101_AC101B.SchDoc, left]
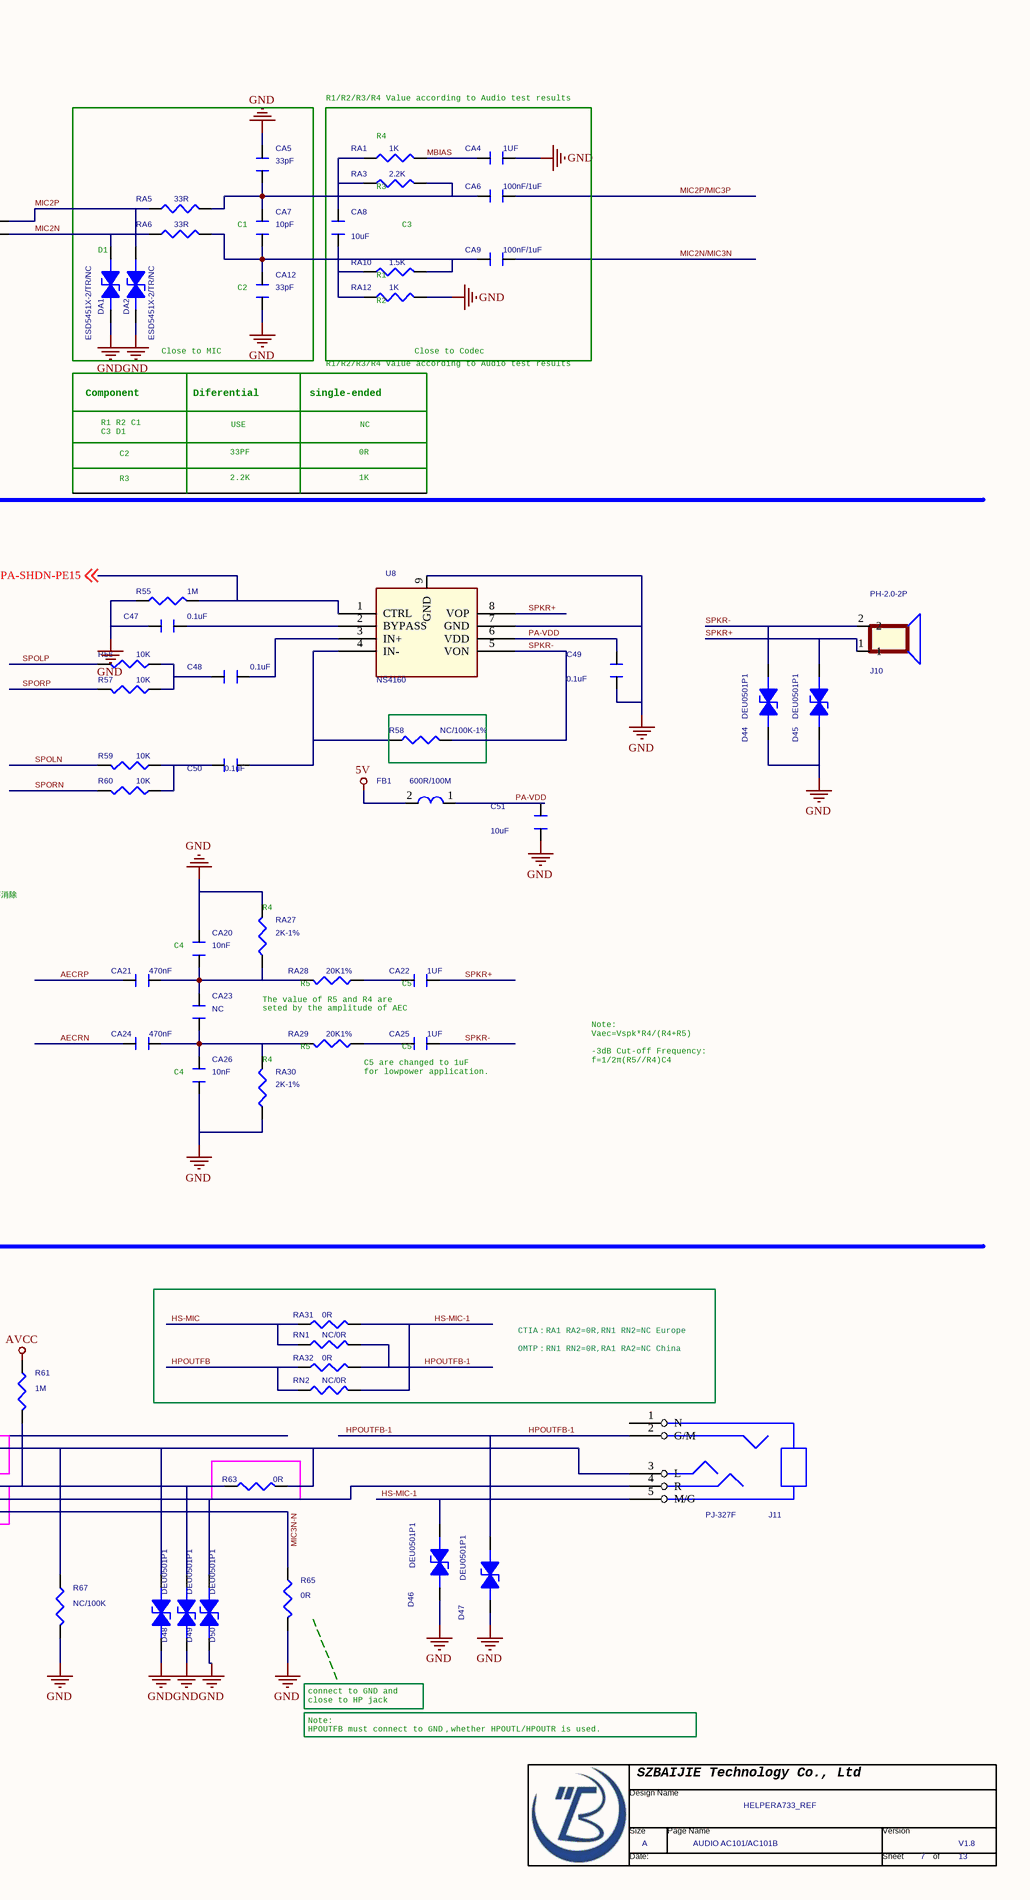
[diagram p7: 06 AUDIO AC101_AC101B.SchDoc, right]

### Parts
(Parts that share a designator on the sheet are numbered #1, #2 ... from top to bottom, then left to right.)
*#7  Page Count: 13  Page Number: 7  Page Size: A  Title: HELPERA733_REF  RevCode: V1.8  Doc: AUDIO AC101/AC101B  (hidden comment: TitleBlock0-BJ)  (graphical)
C47  0.1uF  [C0402]
C48  0.1uF  [C0402]
C49  0.1uF  [C0402]
C50  0.1uF  [C0402]
C51  10uF  [C0402]
C52  1UF  [C0402]
C53  1UF  [C0402]
C54  2.2uF  [C0402]
C55  0.1uF  [C0402]
C56  0.1uF  [C0402]
C57  NC/33pF  [C0402]
C58  NC/33pF  [C0402]
CA1  10uF  [C0603]
CA2  1UF  [C0402]
CA3  4.7uF  [C0402]
CA4  1UF  [C0402]
CA5  33pF  [C0402]
CA6  100nF/1uF  [C0402]
CA7  10pF  [C0402]
CA8  10uF  [C0603]
CA9  100nF/1uF  [C0402]
CA10  2.2uF/1uF  [C0402]
CA11  2.2uF  [C0402]
CA12  33pF  [C0402]
CA13  NC  [C0402]
CA14  1uF/0.47uF  [C0402]
CA15  1uF/0.1uF  [C0402]
CA16  1UF  [C0402]
CA17  2.2uF  [C0402]
CA18  10uF  [C0603]
CA19  2.2uF  [C0402]
CA20  10nF  [C0402]
CA21  470nF  [C0402]
CA22  1UF  [C0402]
CA23  NC  [C0402]
CA24  470nF  [C0402]
CA25  1UF  [C0402]
CA26  10nF  [C0402]
CA27  33pF  [C0402]
D44  DEU0501P1  [ESD0402]
D45  DEU0501P1  [ESD0402]
D46  DEU0501P1  [ESD0402]
D47  DEU0501P1  [ESD0402]
D48  DEU0501P1  [ESD0402]
D49  DEU0501P1  [ESD0402]
D50  DEU0501P1  [ESD0402]
DA1  ESD5451X-2/TR/NC  [ESD0402]
DA2  ESD5451X-2/TR/NC  [ESD0402]
FB1  600R/100M  [L0603]
J10  PH-2.0-2P  [SPEAKER]
J11  PJ-327F  [PJ381-2]
MIC1  Micphone  [Micphone Connector]
R55  1M  [R0402]
R56  10K  [R0402]
R57  10K  [R0402]
R58  NC/100K-1%  [R0402]
R59  10K  [R0402]
R60  10K  [R0402]
R61  1M  [R0402]
R62  47K  [R0402]
R63  0R  [R0402]
R64  1K  [R0402]
R65  0R  [R0402]
R66  1K  [R0402]
R67  NC/100K  [R0402]
R68  1K  [R0402]
RA1  1K  [R0402]
RA2  220K  [C0402]
RA3  2.2K  [R0402]
RA4  0R  [R0402]
RA5  33R  [R0402]
RA6  33R  [R0402]
RA7  0R  [R0402]
RA8  NC  [R0402]
RA9  47K  [R0402]
RA10  1.5K  [R0402]
RA11  NC  [R0402]
RA12  1K  [R0402]
RA13  NC  [R0402]
RA14  0R  [R0402]
RA15  0R  [R0402]
RA16  0R  [R0402]
RA17  NC  [R0402]
RA18  0R  [R0402]
RA19  NC  [R0402]
RA20  0R  [R0402]
RA21  0R  [R0402]
RA22  2K  [R0402]
RA23  2K  [R0402]
RA24  2K  [R0402]
RA25  0R  [R0402]
RA26  0R  [R0402]
RA27  2K-1%  [R0603]
RA28  20K1%  [R0603]
RA29  20K1%  [R0603]
RA30  2K-1%  [R0603]
RA31  0R  [R0402]
RA32  0R  [R0402]
RN1  NC/0R  [R0402]
RN2  NC/0R  [R0402]
U8  NS4160  [ESOP-8]
UA1  AC101  [QFN40]  (value not drawn)

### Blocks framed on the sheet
OPTION1: CA2 CA3 CA11 RA2 RA7 RA14 RA15 RA18
OPTION2: CA13 RA8 RA11 RA13 RA17 RA19
R1: RA4

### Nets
5V: FB1.2
AVCC: R61.1
CODEC-AVCC: CA16.2 RA8.2 RA13.1 RA15.1 RA16.2 RA17.2 UA1.25(VDD-IO) UA1.33(VCC-IO/DEVID)  [also labelled CODEC-IO, CODEC-VCC, VCC33-CODEC]
CODEC-CPVDD: RA7.1 RA14.1 RA18.1 RA20.2  [also labelled CODEC-LDOIN, VCC18-CODEC]
GND: C47.2 C49.2 C51.2 C54.1 C57.2 C58.2 CA1.1 CA2.2 CA3.1 CA4.1 CA5.1 CA10.2 CA11.2 CA12.2 CA13.2 CA14.2 CA15.2 CA16.1 CA17.2 CA18.2 CA20.1 CA26.2 D44.1(ANODE) D45.1(ANODE) D46.1(ANODE) D47.1(ANODE) D48.1(ANODE) D49.1(ANODE) D50.1(ANODE) DA1.1(ANODE) DA2.1(ANODE) R55.1 R65.2 R67.2 RA2.1 RA4.2 RA12.2 RA26.2 RA27.2 RA30.1 U8.7(GND) U8.9(GND) UA1.41(GND)
VCC-1V8: RA20.1
VCC-3V3: RA16.1 RA22.2 RA23.2 RA24.1  [also labelled VCC-IO]
AECRN: CA24.2 RA25.1 ; off-sheet AECRN
AECRP: CA21.2 RA21.1 ; off-sheet AECRP
AGND/VRP: RA4.1 UA1.7(AGND/VRP)
AUDIO-BCLK: UA1.29(BCLK) ; off-sheet I2S0-BCLK  [also labelled I2S0-BCLK]
AUDIO-DIN: UA1.27(SDOUT) ; off-sheet I2S0-DIN0  [also labelled I2S0-DIN0]
AUDIO-DOUT: UA1.26(SDIN) ; off-sheet I2S0-DOUT0  [also labelled I2S0-DOUT0]
AUDIO-LRCK: UA1.28(LRCK) ; off-sheet I2S0-LRCK  [also labelled I2S0-LRCK]
AUDIO-MCLK: UA1.30(MCLK) ; off-sheet I2S0-MCLK  [also labelled I2S0-MCLK]
AUDIO-SCK: RA22.1 RA23.1 UA1.31(SDA) UA1.32(SCK) ; off-sheet TWI8-SCK, off-sheet TWI8-SDA  [also labelled AUDIO-SDA, TWI8-SCK, TWI8-SDA]
AVCC/VRA1: CA14.1 RA15.2 UA1.8(AVCC/VRA1)
CODEC-IRQ: RA24.2 UA1.24(IRQ) ; off-sheet CODEC-IRQ
CODEC-RST: RA19.2 ; off-sheet CODEC-RST
CPVDD: CA13.1 RA14.2 UA1.22(CPVDD)
HBIAS: C54.2 R64.2 UA1.2(HBIAS)
HP-DET: R62.1 RA9.1 RA11.2 RA13.2
HP-DET-PE11: RA9.2 ; off-sheet HP-DET-PE11
HPOUTFB: C57.1 CA27.2 R65.1 R68.2 RA32.1 RN2.1 UA1.18(HPOUTFB) ; off-sheet HPOUTFB-2  [also labelled HPOUTFB-2, MIC3N-N]
HPOUTFB-1: D47.2(CATHODE) J11.2(G/M) RA32.2 RN1.2
HPOUTL: C52.2 UA1.17(HPOUTL) ; off-sheet HPOUTL-2  [also labelled HPOUTL-2]
HPOUTR: C53.2 UA1.19(HPOUTR) ; off-sheet HPOUTR-2  [also labelled HPOUTR-2]
HS-MIC: C58.1 CA27.1 R64.1 R66.2 RA31.1 RN1.1 ; off-sheet HS-MIC-2  [also labelled HS-MIC-2]
HS-MIC-1: D46.2(CATHODE) J11.5(M/G) RA31.2 RN2.2
LDOIN/RSTN: CA15.1 RA17.1 RA18.2 RA19.1 UA1.36(LDOIN/RSTN)
LINEINL/MICIN4N: C56.1 UA1.4(LINEINL/MIC4N<MUX_MIC2N>) ; off-sheet MICIN4N  [also labelled MICIN4N]
LINEINR/MICIN4P: C55.1 UA1.3(LINEINR/MIC4P<MUX_MIC2P>) ; off-sheet MICIN4P  [also labelled MICIN4P]
MBIAS: CA4.2 RA1.2 UA1.38(MBIAS)
MIC2N: DA1.2(CATHODE) MIC1.2(-) RA6.1
MIC2N/MIC3N: CA9.1 UA1.39(MIC2N/MIC3N)
MIC2P: DA2.2(CATHODE) MIC1.1(+) RA5.1
MIC2P/MIC3P: CA6.1 UA1.37(MIC2P/MIC3P)
MICIN1N: RA25.2 UA1.1(MIC1N)
MICIN1P: RA21.2 UA1.40(MIC1P)
PA-SHDN-PE15: R55.2 U8.1(CTRL) ; off-sheet PA-SHDN-PE15
PA-VDD: C49.1 C51.1 FB1.1 U8.6(VDD)
SPKR+: CA22.1 D45.2(CATHODE) J10.1 U8.8(VOP)
SPKR-: CA25.1 D44.2(CATHODE) J10.2 R58.2 U8.5(VON)
SPOLN: R59.1 UA1.12(SPOLN)
SPOLP: R56.1 UA1.11(SPOLP)
SPORN: R60.1 UA1.10(SPORN)
SPORP: R57.1 UA1.9(SPORP)
VDD-CORE/HP-DET: CA11.1 RA11.1 UA1.35(VDD-CORE/HP_DET)
VPP/VCC: CA10.1 RA7.2 RA8.1 UA1.15(VPP/VCC)
VRA1/MIC2P: CA2.1 UA1.14(VRA1/MIC2P<MUX_MIC4P>)
VRA2/MIC2N: CA3.2 RA2.2 UA1.13(VRA2/MIC2N<MUX_MIC4N>)
VRN/AGND: RA26.1 UA1.6(VRN/AGND)
VRP/AVCC: CA1.2 UA1.5(VRP/AVCC)
NetC47_1: C47.1 U8.2(BYPASS)
NetC48_1: C48.1 U8.3(IN+)
NetC48_2: C48.2 R56.2 R57.2
NetC50_1: C50.1 R58.1 U8.4(IN-)
NetC50_2: C50.2 R59.2 R60.2
NetC52_1: C52.1 D48.2(CATHODE) J11.3(L) R63.2 R67.1
NetC53_1: C53.1 D50.2(CATHODE) J11.4(R)
NetC55_2: C55.2 R66.1
NetC56_2: C56.2 R68.1
NetCA5_2: CA5.2 CA6.2 CA7.1 RA3.2 RA5.2
NetCA7_2: CA7.2 CA9.2 CA12.1 RA6.2 RA10.2
NetCA8_1: CA8.1 RA1.1 RA3.1
NetCA8_2: CA8.2 RA10.1 RA12.1
NetCA17_1: CA17.1 UA1.34(BYPASS/VDD-CORE)
NetCA18_1: CA18.1 UA1.16(VEE) UA1.20(CPVEE)
NetCA19_1: CA19.1 UA1.23(CPP)
NetCA19_2: CA19.2 UA1.21(CPN)
NetCA20_2: CA20.2 CA21.1 CA23.1 RA27.1 RA28.2
NetCA22_2: CA22.2 RA28.1
NetCA23_2: CA23.2 CA24.1 CA26.1 RA29.2 RA30.2
NetCA25_2: CA25.2 RA29.1
NetD49_2: D49.2(CATHODE) R61.2 R62.2 R63.1

Not connected (* = marked no-connect by the designer): J11 1(N)

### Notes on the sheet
- For AC101, paste resistor 0R
  For AC101B, paste capacitor 4.7uF
- (near CA1) C1
- AC101/AC101B
- AC101
- AC101B
- ECM MIC
- R1/R2/R3/R4 Value according to Audio test results
- option 2
- option 1
- C1
- R1
- C2
- USE
- NC
- 10uF
- 0R
- 2.2uF
- 4.7uF
- 1uF
- MIC1
- (near RA3) R3
- (near RA1) R4
- option 3
- C3
- C4
- RA1
- RA2
- AC107 NC
- 0.47uF
- 0.1uF
- AC107 USE
- (near DA1) D1
- (near CA7) C1
- (near CA10) C2
- RA7
- RA3
- RA4
- RA5
- RA6
- (near CA12) C2
- (near RA10) R1
- (near RA12) R2
- (near RA16) 3.3V 50mA
- NC AC107,use AC101B only support single ECM MIC.
  NC AC107,use AC101 not support ECM MIC.
- NOTE:
- RA8
- Close to MIC
- Close to Codec
- (near CA15) C4
- (near CA14) C3
- (near CA16) 为了与AC101兼容省电阻，默认选择上拉；
  DEVID有两组I2C地址，为了一组I2C控制两颗AC101B使用；
- Component
- R1 R2 C1
  C3 D1
- Diferential
- single-ended
- R3
- 33PF
- 2.2K
- 1K
- (near RA20) 1.8V 50mA
- SPEAKER
- (near RA21) RA3
- (near RA25) RA4
- AEC
- 回声消除
- (near CA20) C4
- (near RA27) R4
- The value of R5 and R4 are
  seted by the amplitude of AEC
- (near RA28) R5
- (near CA22) C5
- Note:
  Vaec=Vspk*R4/(R4+R5)
  -3dB Cut-off Frequency:
  f=1/2π(R5//R4)C4
- HEADPHONE
- (near CA26) C4
- (near RA30) R4
- (near RA29) R5
- C5 are changed to 1uF
  for lowpower application.
- (near CA25) C5
- SPEAKEFR
- HP_JACK
- PJ-327F  PCB封装参考此图
  PJ-327F  PCB package refer to this figure
- L
- R
- GND
- MIC
- CTIA：RA1 RA2=0R,RN1 RN2=NC Europe
  OMTP：RN1 RN2=0R,RA1 RA2=NC China
- TYPEC AUDIO
- CTIA
- (near C54) Close to Codec
- Note:
- (near *#7) Note:
  HPOUTFB must connect to GND，whether HPOUTL/HPOUTR is used.
- connect to GND and
  close to HP jack
- (near C56) TYPE-C audio also need those circuit.

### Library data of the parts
C47-C49 C51 = C-C0402_Dup1
C50 = CAPACITOR_0_Dup1: options: 4890-2
C52 C53 = CAP NP_0
C54-C58 CA4-CA7 CA9 CA12 CA20-CA27 = C-C0402_Dup1: Parameter: C0402-X5R
CA1 CA2 CA10 CA16 = CAPACITOR_0_Dup1: PAGE: 2; ROOM: POWER
CA3 CA15 = CAPACITOR_0: PAGE: 1; ROOM: AC100
CA8 = C-C0603: Parameter: C0402-X5R
CA11 = CAPACITOR_0_Dup1: ROOM: POWER; PAGE: 2
CA13 CA14 CA17-CA19 = CAPACITOR_0: ROOM: AC100; PAGE: 1
D44 D45 = ESD9B5VL: ID: DE-E0001; options: 4890-1
D46-D50 = ESD9B5VL: ID: DE-E0001
DA1 DA2 = ESD9B5VL_0: Parameter: ESD0402，3PF; ID: DE-E0001
FB1 = INDUCTOR_0_Dup1: as FB2 on sheet 10 Ethernet
J10 = SPEAKER_0
J11 = PJ381-2_1
MIC1 = Micphone_0: mypage: 13
R55 R58 R64 R66 R68 RA1 RA3 RA5 RA6 RA10 RA12 = R-R0402-5%_Dup3
R56 R57 R59 R60 = RESISTOR_Dup1: options: 4890-2
R61-R63 R65 R67 RA31 RA32 RN1 RN2 = R-R0402-5%
RA2 RA4 RA7-RA9 RA11 RA13-RA20 RA22-RA24 RA26 = R_Dup1: ROOM: AC100
RA21 RA25 = R-R0402-5%_Dup1
RA27-RA30 = R-R0603-1%
U8 = LY8006_1
UA1 = AC101&AC101B V0_1.2

## Sheet 05 TF_KEY_RTC.SchDoc
size 386 x 246 mm
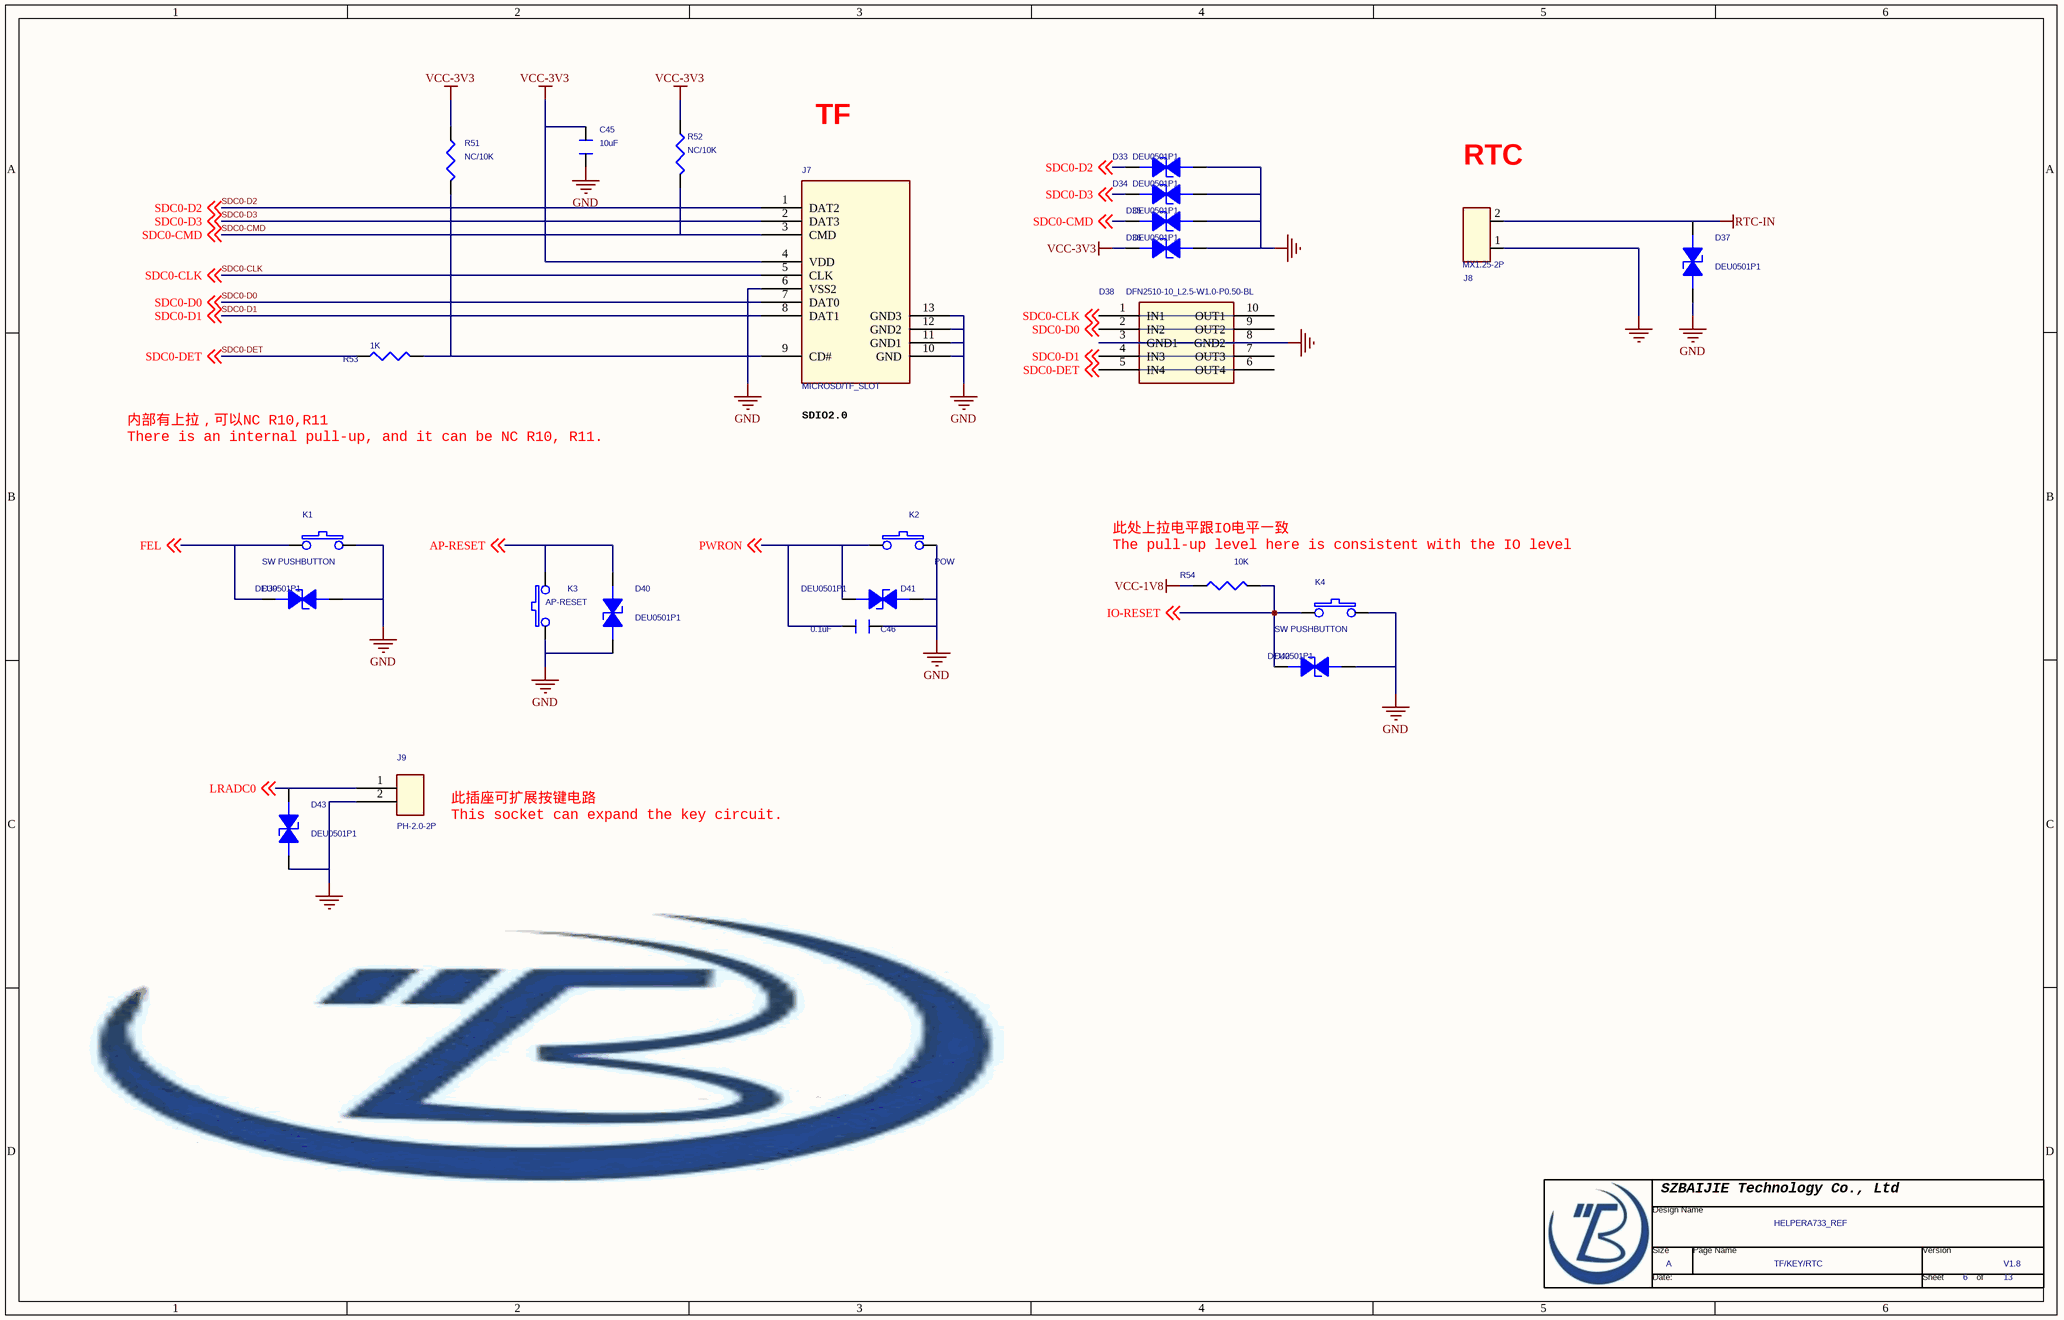
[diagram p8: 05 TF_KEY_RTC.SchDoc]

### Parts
(Parts that share a designator on the sheet are numbered #1, #2 ... from top to bottom, then left to right.)
*#8  Page Count: 13  Page Number: 6  Page Size: A  Title: HELPERA733_REF  RevCode: V1.8  Doc: TF/KEY/RTC  (hidden comment: TitleBlock0-BJ)  (graphical)
C45  10uF  [C0603]
C46  0.1uF  [C0402]
D33  DEU0501P1  [ESD0402]
D34  DEU0501P1  [ESD0402]
D35  DEU0501P1  [ESD0402]
D36  DEU0501P1  [ESD0402]
D37  DEU0501P1  [ESD0402]
D38  DFN2510-10_L2.5-W1.0-P0.50-BL  [RCLAMP0524P]
D39  DEU0501P1  [ESD0402]
D40  DEU0501P1  [ESD0402]
D41  DEU0501P1  [ESD0402]
D42  DEU0501P1  [ESD0402]
D43  DEU0501P1  [ESD0402]
J7  MICROSD/TF_SLOT  [tf_push1]
J8  MX1.25-2P  [MX1.25-2P]
J9  PH-2.0-2P  [PH-2.0-2P]
K1  SW PUSHBUTTON  [KEY_3X4]
K2  POW  [KEY_3X4]
K3  AP-RESET  [KEY_3X4]
K4  SW PUSHBUTTON  [KEY_3X4]
R51  NC/10K  [R0402]
R52  NC/10K  [R0402]
R53  1K  [R0402]
R54  10K  [R0402]

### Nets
GND: C45.1 C46.2 D33.1(ANODE) D34.1(ANODE) D35.1(ANODE) D36.1(ANODE) D37.1(ANODE) D38.3(GND1) D38.8(GND2) D39.2(CATHODE) D40.1(ANODE) D41.1(ANODE) D42.2(CATHODE) D43.1(ANODE) J7.6(VSS2) J7.10(GND) J7.11(GND1) J7.12(GND2) J7.13(GND3) J8.1 J9.2 K1.2 K2.1 K3.1 K4.2
RTC-IN: D37.2(CATHODE) J8.2
VCC-1V8: R54.1
VCC-3V3: C45.2 D36.2(CATHODE) J7.4(VDD) R51.1 R52.1
AP-RESET: D40.2(CATHODE) K3.2 ; off-sheet AP-RESET
FEL: D39.1(ANODE) K1.1 ; off-sheet FEL
IO-RESET: D42.1(ANODE) K4.1 R54.2 ; off-sheet IO-RESET
LRADC0: D43.2(CATHODE) J9.1 ; off-sheet LRADC0
PWRON: C46.1 D41.2(CATHODE) K2.2 ; off-sheet PWRON
SDC0-CLK: D38.1(IN1) D38.10(OUT1) J7.5(CLK) ; off-sheet SDC0-CLK
SDC0-CMD: D35.2(CATHODE) J7.3(CMD) R52.2 ; off-sheet SDC0-CMD
SDC0-D0: D38.2(IN2) D38.9(OUT2) J7.7(DAT0) ; off-sheet SDC0-D0
SDC0-D1: D38.4(IN3) D38.7(OUT3) J7.8(DAT1) ; off-sheet SDC0-D1
SDC0-D2: D33.2(CATHODE) J7.1(DAT2) ; off-sheet SDC0-D2
SDC0-D3: D34.2(CATHODE) J7.2(DAT3) ; off-sheet SDC0-D3
SDC0-DET: D38.5(IN4) D38.6(OUT4) R53.1 ; off-sheet SDC0-DET
NetJ7_9: J7.9(CD#) R51.2 R53.2

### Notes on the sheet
- TF
- (near J8) RTC
- 内部有上拉，可以NC R10,R11
  There is an internal pull-up, and it can be NC R10, R11.
- SDIO2.0
- (near R54) 此处上拉电平跟IO电平一致
  The pull-up level here is consistent with the IO level
- 此插座可扩展按键电路
  This socket can expand the key circuit.

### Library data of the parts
C45 = CAPACITOR_0_Dup1: PAGE: 2
C46 = CAPACITOR_0_Dup1
D33-D37 D39-D43 = 1_1.5KE100A_Dup1: as D61 on sheet 11 OTG_host_HUB
D38 = rRClamp0524P
J7 = SDMMC SLOT_0
J8 = CON6_0: CON;HDR,6PX1,1MM,R/A,H1.9,SMT; VENDER P/N: 3800-6; VENDER: E&T; P/N: XXXXXXXXXXXX; device: CONN_ENT3800_6_1
J9 = CON2
K2 K3 = SW PUSHBUTTON
R51-R53 = R_Dup6
R54 = R_Dup3

## Sheet 04 LCD.SchDoc
size 513 x 386 mm
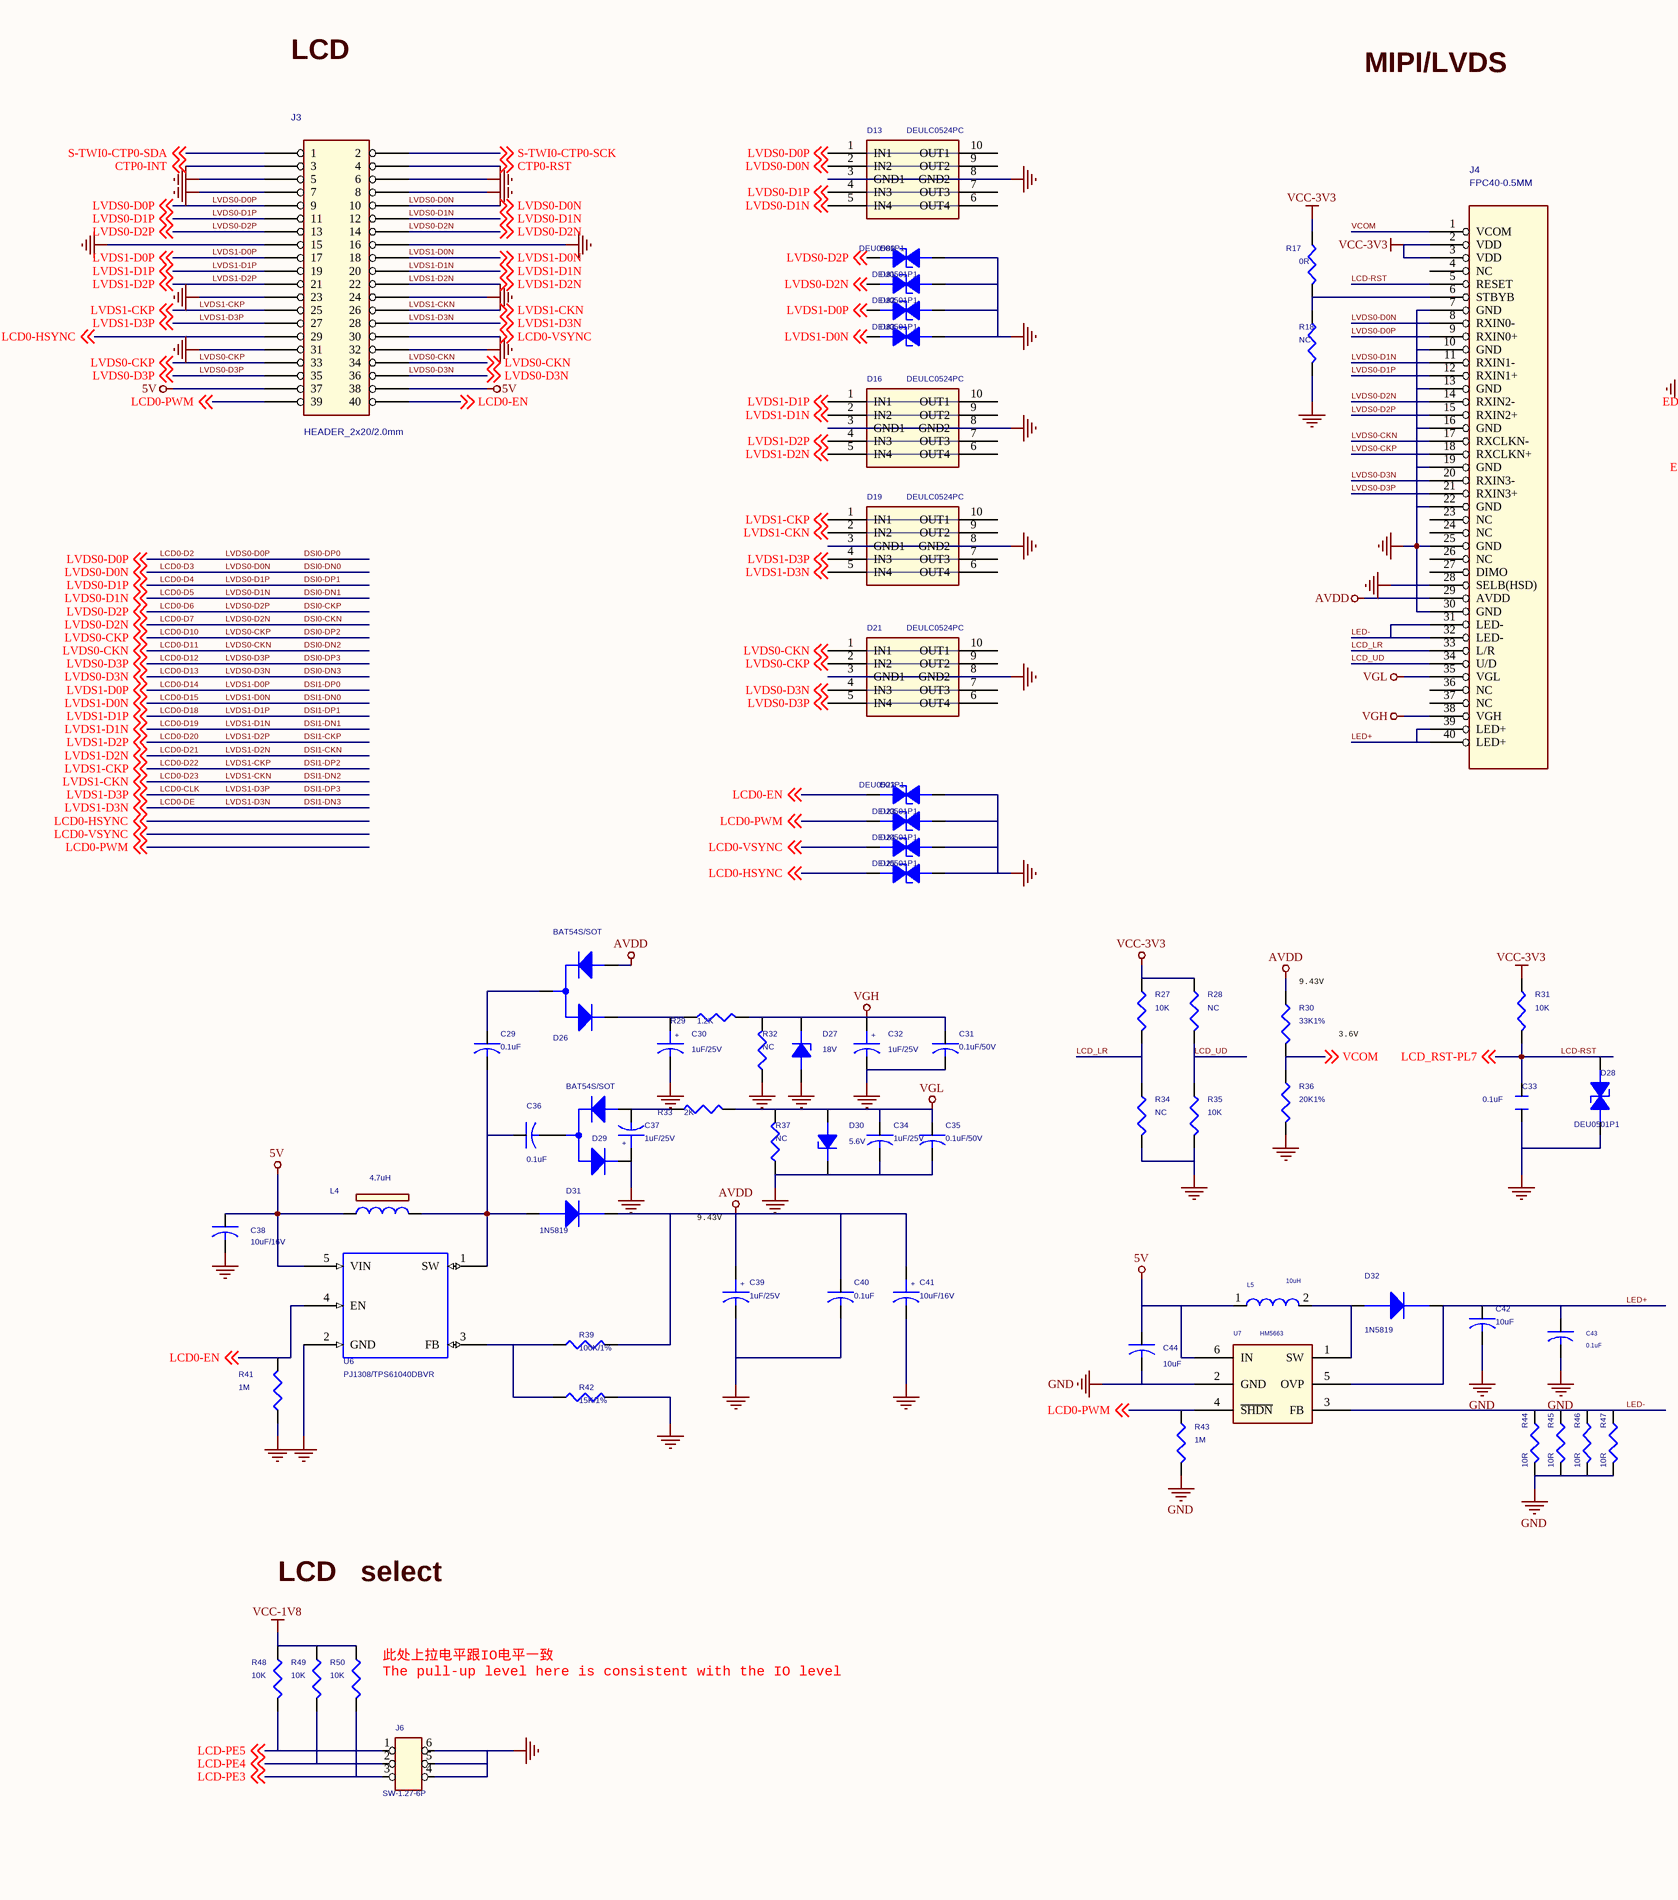
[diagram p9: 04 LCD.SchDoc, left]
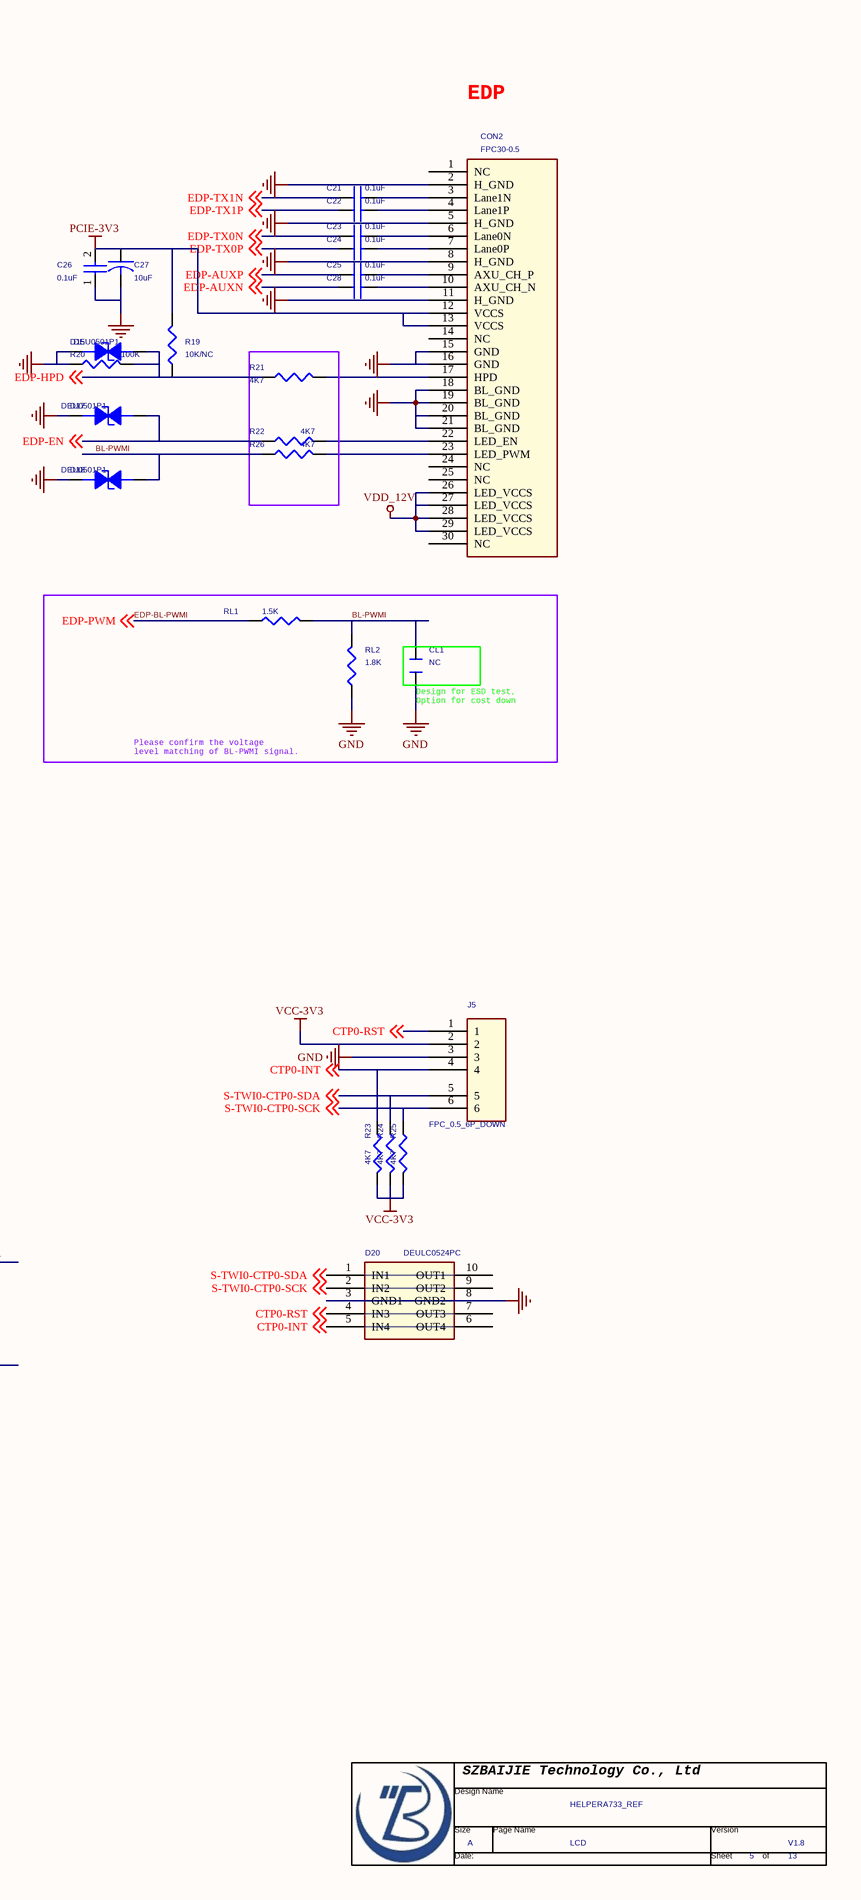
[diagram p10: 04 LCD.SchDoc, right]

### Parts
(Parts that share a designator on the sheet are numbered #1, #2 ... from top to bottom, then left to right.)
*#9  Page Count: 13  Page Number: 5  Page Size: A  Title: HELPERA733_REF  RevCode: V1.8  Doc: LCD  (hidden comment: TitleBlock0-BJ)  (graphical)
C21  0.1uF  [C0402]
C22  0.1uF  [C0402]
C23  0.1uF  [C0402]
C24  0.1uF  [C0402]
C25  0.1uF  [C0402]
C26  0.1uF  [C0402]
C27  10uF  [C0603]
C28  0.1uF  [C0402]
C29  0.1uF  [C0402]
C30  1uF/25V  [C0805]
C31  0.1uF/50V  [C0402]
C32  1uF/25V  [C0805]
C33  0.1uF  [C0402]
C34  1uF/25V  [C0805]
C35  0.1uF/50V  [C0402]
C36  0.1uF  [C0402]
C37  1uF/25V  [C0805]
C38  10uF/16V  [C0603]
C39  1uF/25V  [C0805]
C40  0.1uF  [C0402]
C41  10uF/16V  [C0603]
C42  10uF  [C0603]
C43  0.1uF  [C0402]
C44  10uF  [C0603]
CL1  NC  [C0402]
CON2  FPC30-0.5  [FPC30-0.5-1]
D13  DEULC0524PC  [DFN2510-10_L2.5-W1.0-P0.50-BL]
D15  DEU0501P1  [ESD0402]
D16  DEULC0524PC  [DFN2510-10_L2.5-W1.0-P0.50-BL]
D17  DEU0501P1  [ESD0402]
D18  DEU0501P1  [ESD0402]
D19  DEULC0524PC  [DFN2510-10_L2.5-W1.0-P0.50-BL]
D20  DEULC0524PC  [DFN2510-10_L2.5-W1.0-P0.50-BL]
D21  DEULC0524PC  [DFN2510-10_L2.5-W1.0-P0.50-BL]
D22  DEU0501P1  [ESD0402]
D23  DEU0501P1  [ESD0402]
D24  DEU0501P1  [ESD0402]
D25  DEU0501P1  [ESD0402]
D26  BAT54S/SOT  [SOT23]
D27  18V  [D0805]
D28  DEU0501P1  [ESD0402]
D29  BAT54S/SOT  [SOT23]
D30  5.6V  [D0805]
D31  1N5819  [D0805]
D32  1N5819  [SOD323]
D80  DEU0501P1  [ESD0402]
D81  DEU0501P1  [ESD0402]
D82  DEU0501P1  [ESD0402]
D83  DEU0501P1  [ESD0402]
J3  HEADER_2x20/2.0mm  [HDR2X20/2.0]
J4  FPC40-0.5MM  [FPC40-0.5MM-UP]
J5  FPC_0.5_6P_DOWN  [FPC_0.5_6P_DOWN]
J6  SW-1.27-6P  [SW-1.27-6P]
L4  4.7uH  [4018]
L5  10uH  [4018]
R17  0R  [R0402]
R18  NC  [R0402]
R19  10K/NC  [R0402]
R20  100K  [R0402]
R21  4K7  [R0402]
R22  4K7  [R0402]
R23  4K7  [R0402]
R24  4K7  [R0402]
R25  4K7  [R0402]
R26  4K7  [R0402]
R27  10K  [R0402]
R28  NC  [R0402]
R29  1.2K  [R0402]
R30  33K1%  [R0402]
R31  10K  [R0402]
R32  NC  [R0402]
R33  2K  [R0402]
R34  NC  [R0402]
R35  10K  [R0402]
R36  20K1%  [R0402]
R37  NC  [R0402]
R39  100K/1%  [R0402]
R41  1M  [R0402]
R42  15K/1%  [R0402]
R43  1M  [R0402]
R44  10R  [R0402]
R45  10R  [R0402]
R46  10R  [R0402]
R47  10R  [R0402]
R48  10K  [R0402]
R49  10K  [R0402]
R50  10K  [R0402]
RL1  1.5K  [R0402]
RL2  1.8K  [R0402]
U6  PJ1308/TPS61040DBVR  [SOT23-5]
U7  HM5663  [SOT89-5]

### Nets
5V: C38.1 C44.1 J3.37 J3.38 L4.1 L5.1 U6.5(VIN) U7.6(IN)
AVDD: C39.1 C40.1 C41.1 D26.1 D31.2(CATHODE) J4.29(AVDD) R30.1 R39.2
GND: C26.1 C27.2 C30.2 C31.2 C32.2 C33.1 C34.2 C35.2 C37.1 C38.2 C39.2 C40.2 C41.2 C42.2 C43.2 C44.2 CL1.2 CON2.2(H_GND) CON2.5(H_GND) CON2.8(H_GND) CON2.11(H_GND) CON2.15(GND) CON2.16(GND) CON2.18(BL_GND) CON2.19(BL_GND) CON2.20(BL_GND) CON2.21(BL_GND) D13.3(GND1) D13.8(GND2) D15.1(ANODE) D16.3(GND1) D16.8(GND2) D17.1(ANODE) D18.1(ANODE) D19.3(GND1) D19.8(GND2) D20.3(GND1) D20.8(GND2) D21.3(GND1) D21.8(GND2) D22.2(CATHODE) D23.2(CATHODE) D24.2(CATHODE) D25.2(CATHODE) D27.1(ANODE) D28.2(CATHODE) D29.2 D30.2(CATHODE) D80.2(CATHODE) D81.2(CATHODE) D82.2(CATHODE) D83.2(CATHODE) J3.5 J3.6 J3.7 J3.8 J3.15 J3.16 J3.23 J3.24 J3.31 J3.32 J4.7(GND) J4.10(GND) J4.13(GND) J4.16(GND) J4.19(GND) J4.22(GND) J4.25(GND) J4.28(SELB(HSD)) J4.30(GND) J5.3 J6.4 J6.5 J6.6 R18.2 R20.1 R32.1 R34.2 R35.2 R36.2 R37.1 R41.1 R42.2 R43.2 R44.2 R45.2 R46.2 R47.2 RL2.1 U6.2(GND) U7.2(GND)
PCIE-3V3: C26.2 C27.1 CON2.12(VCCS) CON2.13(VCCS) R19.2
VCC-1V8: R48.1 R49.1 R50.1
VCC-3V3: J4.2(VDD) J4.3(VDD) J5.2 R17.1 R23.2 R24.2 R25.2 R27.1 R28.1 R31.1
VDD_12V: CON2.26(LED_VCCS) CON2.27(LED_VCCS) CON2.28(LED_VCCS) CON2.29(LED_VCCS)  [project net DCIN]
VGH: C31.1 C32.1 D27.2(CATHODE) J4.38(VGH) R29.2 R32.2
VGL: C34.1 C35.1 D30.1(ANODE) J4.35(VGL) R33.2 R37.2
BL-PWMI: CL1.1 D18.2(CATHODE) R26.1 RL1.2 RL2.2
CTP0-INT: D20.5(IN4) D20.6(OUT4) J3.3 J5.4 R23.1 ; off-sheet CTP0-INT
CTP0-RST: D20.4(IN3) D20.7(OUT3) J3.4 J5.1 ; off-sheet CTP0-RST
DSI0-CKN: D81.1(ANODE) J3.14 J4.14(RXIN2-) ; off-sheet LVDS0-D2N  [also labelled LCD0-D7, LVDS0-D2N]
DSI0-CKP: D80.1(ANODE) J3.13 J4.15(RXIN2+) ; off-sheet LVDS0-D2P  [also labelled LCD0-D6, LVDS0-D2P]
DSI0-DN0: D13.2(IN2) D13.9(OUT2) J3.10 J4.8(RXIN0-) ; off-sheet LVDS0-D0N  [also labelled LCD0-D3, LVDS0-D0N]
DSI0-DN1: D13.5(IN4) D13.6(OUT4) J3.12 J4.11(RXIN1-) ; off-sheet LVDS0-D1N  [also labelled LCD0-D5, LVDS0-D1N]
DSI0-DN2: D21.1(IN1) D21.10(OUT1) J3.34 J4.17(RXCLKN-) ; off-sheet LVDS0-CKN  [also labelled LCD0-D11, LVDS0-CKN]
DSI0-DN3: D21.4(IN3) D21.7(OUT3) J3.36 J4.20(RXIN3-) ; off-sheet LVDS0-D3N  [also labelled LCD0-D13, LVDS0-D3N]
DSI0-DP0: D13.1(IN1) D13.10(OUT1) J3.9 J4.9(RXIN0+) ; off-sheet LVDS0-D0P  [also labelled LCD0-D2, LVDS0-D0P]
DSI0-DP1: D13.4(IN3) D13.7(OUT3) J3.11 J4.12(RXIN1+) ; off-sheet LVDS0-D1P  [also labelled LCD0-D4, LVDS0-D1P]
DSI0-DP2: D21.2(IN2) D21.9(OUT2) J3.33 J4.18(RXCLKN+) ; off-sheet LVDS0-CKP  [also labelled LCD0-D10, LVDS0-CKP]
DSI0-DP3: D21.5(IN4) D21.6(OUT4) J3.35 J4.21(RXIN3+) ; off-sheet LVDS0-D3P  [also labelled LCD0-D12, LVDS0-D3P]
DSI1-CKN: D16.5(IN4) D16.6(OUT4) J3.22 ; off-sheet LVDS1-D2N  [also labelled LCD0-D21, LVDS1-D2N]
DSI1-CKP: D16.4(IN3) D16.7(OUT3) J3.21 ; off-sheet LVDS1-D2P  [also labelled LCD0-D20, LVDS1-D2P]
DSI1-DN0: D83.1(ANODE) J3.18 ; off-sheet LVDS1-D0N  [also labelled LCD0-D15, LVDS1-D0N]
DSI1-DN1: D16.2(IN2) D16.9(OUT2) J3.20 ; off-sheet LVDS1-D1N  [also labelled LCD0-D19, LVDS1-D1N]
DSI1-DN2: D19.2(IN2) D19.9(OUT2) J3.26 ; off-sheet LVDS1-CKN  [also labelled LCD0-D23, LVDS1-CKN]
DSI1-DN3: D19.5(IN4) D19.6(OUT4) J3.28 ; off-sheet LVDS1-D3N  [also labelled LCD0-DE, LVDS1-D3N]
DSI1-DP0: D82.1(ANODE) J3.17 ; off-sheet LVDS1-D0P  [also labelled LCD0-D14, LVDS1-D0P]
DSI1-DP1: D16.1(IN1) D16.10(OUT1) J3.19 ; off-sheet LVDS1-D1P  [also labelled LCD0-D18, LVDS1-D1P]
DSI1-DP2: D19.1(IN1) D19.10(OUT1) J3.25 ; off-sheet LVDS1-CKP  [also labelled LCD0-D22, LVDS1-CKP]
DSI1-DP3: D19.4(IN3) D19.7(OUT3) J3.27 ; off-sheet LVDS1-D3P  [also labelled LCD0-CLK, LVDS1-D3P]
EDP-AUXN: C28.1 ; off-sheet EDP-AUXN
EDP-AUXP: C25.1 ; off-sheet EDP-AUXP
EDP-BL-PWMI: RL1.1 ; off-sheet EDP-PWM  [also labelled EDP-PWM]
EDP-EN: D17.2(CATHODE) R22.1 ; off-sheet EDP-EN
EDP-HPD: D15.2(CATHODE) R19.1 R20.2 R21.1 ; off-sheet EDP-HPD
EDP-TX0N: C23.1 ; off-sheet EDP-TX0N
EDP-TX0P: C24.1 ; off-sheet EDP-TX0P
EDP-TX1N: C21.1 ; off-sheet EDP-TX1N
EDP-TX1P: C22.1 ; off-sheet EDP-TX1P
LCD0-EN: D22.1(ANODE) J3.40 R41.2 U6.4(EN) ; off-sheet LCD0-EN
LCD0-HSYNC: D25.1(ANODE) J3.29 ; off-sheet LCD0-HSYNC
LCD0-PWM: D23.1(ANODE) J3.39 R43.1 U7.4(~{SHDN}) ; off-sheet LCD0-PWM
LCD0-VSYNC: D24.1(ANODE) J3.30 ; off-sheet LCD0-VSYNC
LCD-PE3: J6.3 R50.2 ; off-sheet LCD-PE3
LCD-PE4: J6.2 R49.2 ; off-sheet LCD-PE4
LCD-PE5: J6.1 R48.2 ; off-sheet LCD-PE5
LCD-RST: C33.2 D28.1(ANODE) J4.5(RESET) R31.2 ; off-sheet LCD_RST-PL7  [also labelled LCD_RST-PL7]
LCD_LR: J4.33(L/R) R27.2 R34.1
LCD_UD: J4.34(U/D) R28.2 R35.1
LED+: C42.1 C43.1 D32.2(CATHODE) J4.39(LED+) J4.40(LED+) U7.5(OVP)
LED-: J4.31(LED-) J4.32(LED-) R44.1 R45.1 R46.1 R47.1 U7.3(FB)
S-TWI0-CTP0-SCK: D20.2(IN2) D20.9(OUT2) J3.2 J5.6 R25.1 ; off-sheet S-TWI0-CTP0-SCK
S-TWI0-CTP0-SDA: D20.1(IN1) D20.10(OUT1) J3.1 J5.5 R24.1 ; off-sheet S-TWI0-CTP0-SDA
VCOM: J4.1(VCOM) R30.2 R36.1 ; off-sheet VCOM
NetC21_2: C21.2 CON2.3(Lane1N)
NetC22_2: C22.2 CON2.4(Lane1P)
NetC23_2: C23.2 CON2.6(Lane0N)
NetC24_2: C24.2 CON2.7(Lane0P)
NetC25_2: C25.2 CON2.9(AXU_CH_P)
NetC28_2: C28.2 CON2.10(AXU_CH_N)
NetC29_1: C29.1 D26.3
NetC29_2: C29.2 C36.1 D31.1(ANODE) L4.2 U6.1(SW)
NetC30_1: C30.1 D26.2 R29.1
NetC36_2: C36.2 D29.3
NetC37_2: C37.2 D29.1 R33.1
NetCON2_17: CON2.17(HPD) R21.2
NetCON2_22: CON2.22(LED_EN) R22.2
NetCON2_23: CON2.23(LED_PWM) R26.2
NetD32_1: D32.1(ANODE) L5.2 U7.1(SW)
NetJ4_6: J4.6(STBYB) R17.2 R18.1
NetR39_1: R39.1 R42.1 U6.3(FB)

Not connected (* = marked no-connect by the designer): CON2 1(NC) 14(NC) 24(NC) 25(NC) 30(NC); J4 4(NC) 23(NC) 24(NC) 26(NC) 27(DIMO) 36(NC) 37(NC)

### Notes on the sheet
- LCD
- MIPI/LVDS
- EDP
- (near CL1) Design for ESD test,
  Option for cost down
- Please confirm the voltage
  level matching of BL-PWMI signal.
- (near R30) 9.43V
- 3.6V
- 9.43V
- LCD   select
- (near R50) 此处上拉电平跟IO电平一致
  The pull-up level here is consistent with the IO level

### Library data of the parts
C21 = CAP NP_1: cap,100.00nF,+/-10%,25V,X5R,C0402; Tolerance: 10%; Priority: A
C22-C24 = CAP NP_3: cap,100.00nF,+/-10%,25V,X5R,C0402; Tolerance: 10%; Priority: A
C25 C28 = CAP NP_3: cap,100.00nF,+/-10%,25V,X5R,C0402; Priority: A; Tolerance: 10%
C26 = CAP NP_0
C27 C29 C31 C34-C36 C38 C40 C42 C44 = C_Dup1
C30 C32 C37 C39 C41 = CAP POL
C33 = CAPACITOR_0_Dup1
C43 = C
CL1 = C-C0402_Dup1: Parameter: C0402-X5R
CON2 = CN_2
D13 D16 D19-D21 = rRClamp0524P
D15 D17 D18 D22-D25 D28 D80-D83 = 1_1.5KE100A_Dup1: as D61 on sheet 11 OTG_host_HUB
D27 D30 = DIODE BREAKDOWN_1
D31 D32 = BAS21/SOT_1
J3 = HEADER 20X2_1: Populate: YES
J4 = HEADER 20X2_3: Populate: YES
J5 = connet_0
J6 = CON4_4
L4 = CHOKE TORROID-FERRITE
L5 = INDUCTOR_Dup1
R17-R28 R30 R31 R34-R36 R39 R42-R50 = R_Dup3
R29 R32 R33 R37 R41 = RESISTOR_Dup2
RL1 RL2 = R-R0402-5%_Dup3
U6 = X9C102/SO_2
U7 = PT4110_0_Dup1

## Sheet 03 CAMERA.SchDoc
size 386 x 246 mm
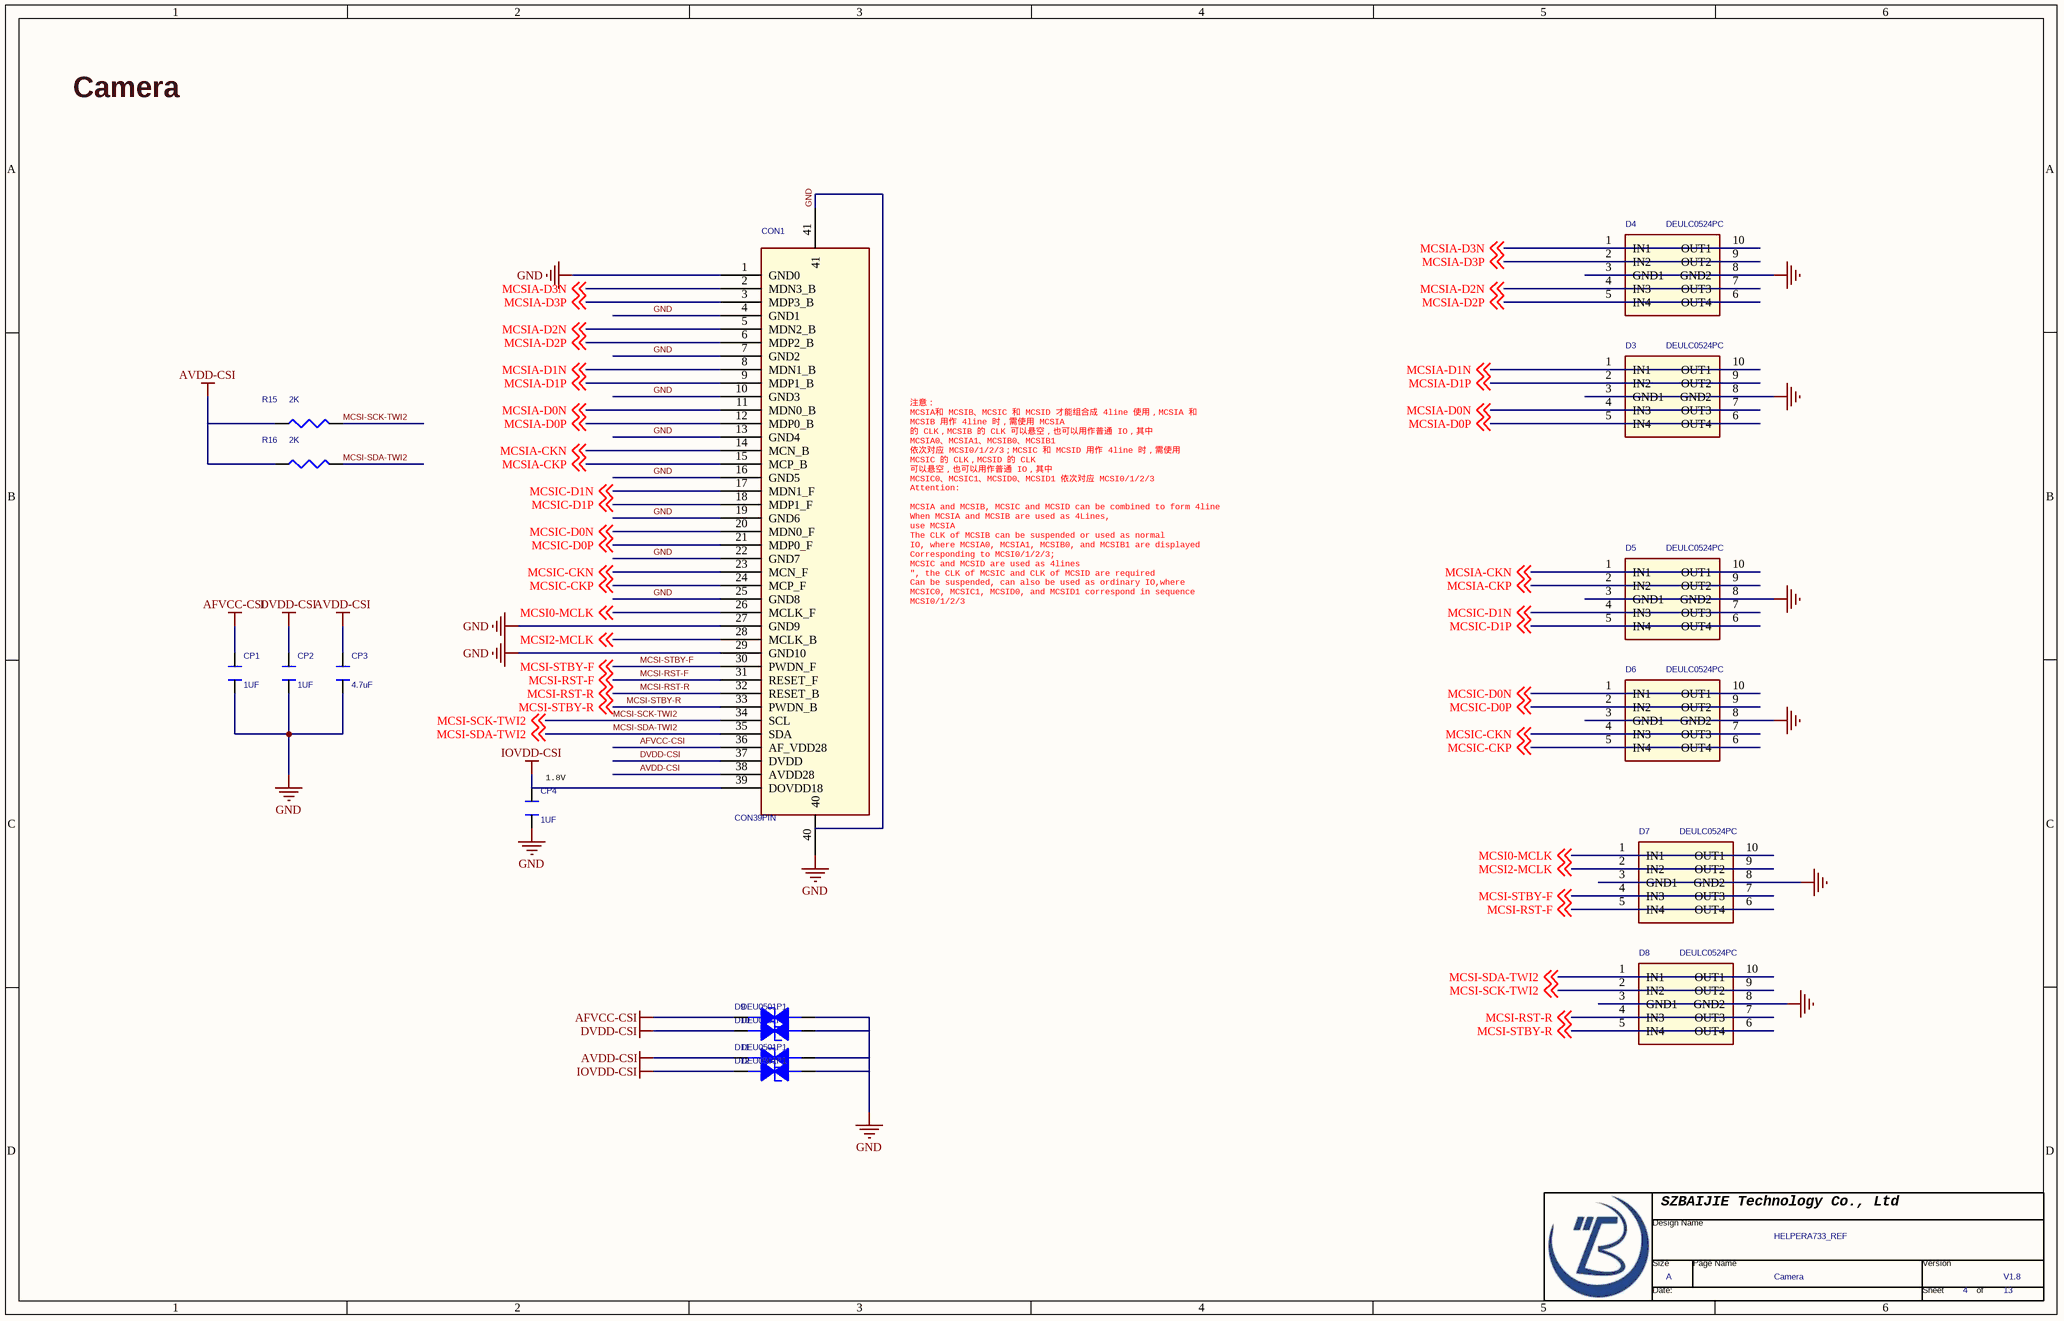
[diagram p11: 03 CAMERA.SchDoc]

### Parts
(Parts that share a designator on the sheet are numbered #1, #2 ... from top to bottom, then left to right.)
*#10  Page Count: 13  Page Number: 4  Page Size: A  Title: HELPERA733_REF  RevCode: V1.8  Doc: Camera  (hidden comment: TitleBlock0-BJ)  (graphical)
CON1  CON39PIN  [FH35C-39S-0.3SHW]
CP1  1UF  [C0603]
CP2  1UF  [C0603]
CP3  4.7uF  [C0603]
CP4  1UF  [C0603]
D3  DEULC0524PC  [DFN2510-10_L2.5-W1.0-P0.50-BL]
D4  DEULC0524PC  [DFN2510-10_L2.5-W1.0-P0.50-BL]
D5  DEULC0524PC  [DFN2510-10_L2.5-W1.0-P0.50-BL]
D6  DEULC0524PC  [DFN2510-10_L2.5-W1.0-P0.50-BL]
D7  DEULC0524PC  [DFN2510-10_L2.5-W1.0-P0.50-BL]
D8  DEULC0524PC  [DFN2510-10_L2.5-W1.0-P0.50-BL]
D9  DEU0501P1  [ESD0402]
D10  DEU0501P1  [ESD0402]
D11  DEU0501P1  [ESD0402]
D12  DEU0501P1  [ESD0402]
R15  2K  [R0402]
R16  2K  [R0402]

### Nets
AFVCC-CSI: CON1.36(AF_VDD28) CP1.1 D9.2(CATHODE)
AVDD-CSI: CON1.38(AVDD28) CP3.1 D11.2(CATHODE) R15.1 R16.1
DVDD-CSI: CON1.37(DVDD) CP2.1 D10.2(CATHODE)
GND: CON1.1(GND0) CON1.4(GND1) CON1.7(GND2) CON1.10(GND3) CON1.13(GND4) CON1.16(GND5) CON1.19(GND6) CON1.22(GND7) CON1.25(GND8) CON1.27(GND9) CON1.29(GND10) CON1.40 CON1.41 CP1.2 CP2.2 CP3.2 CP4.2 D3.3(GND1) D3.8(GND2) D4.3(GND1) D4.8(GND2) D5.3(GND1) D5.8(GND2) D6.3(GND1) D6.8(GND2) D7.3(GND1) D7.8(GND2) D8.3(GND1) D8.8(GND2) D9.1(ANODE) D10.1(ANODE) D11.1(ANODE) D12.1(ANODE)
IOVDD-CSI: CON1.39(DOVDD18) CP4.1 D12.2(CATHODE)
MCSI0-MCLK: CON1.26(MCLK_F) D7.1(IN1) D7.10(OUT1) ; off-sheet MCSI0-MCLK
MCSI2-MCLK: CON1.28(MCLK_B) D7.2(IN2) D7.9(OUT2) ; off-sheet MCSI2-MCLK
MCSI-RST-F: CON1.31(RESET_F) D7.5(IN4) D7.6(OUT4) ; off-sheet MCSI-RST-F
MCSI-RST-R: CON1.32(RESET_B) D8.4(IN3) D8.7(OUT3) ; off-sheet MCSI-RST-R
MCSI-SCK-TWI2: CON1.34(SCL) D8.2(IN2) D8.9(OUT2) R15.2 ; off-sheet MCSI-SCK-TWI2
MCSI-SDA-TWI2: CON1.35(SDA) D8.1(IN1) D8.10(OUT1) R16.2 ; off-sheet MCSI-SDA-TWI2
MCSI-STBY-F: CON1.30(PWDN_F) D7.4(IN3) D7.7(OUT3) ; off-sheet MCSI-STBY-F
MCSI-STBY-R: CON1.33(PWDN_B) D8.5(IN4) D8.6(OUT4) ; off-sheet MCSI-STBY-R
MCSIA-CKN: CON1.14(MCN_B) D5.1(IN1) D5.10(OUT1) ; off-sheet MCSIA-CKN
MCSIA-CKP: CON1.15(MCP_B) D5.2(IN2) D5.9(OUT2) ; off-sheet MCSIA-CKP
MCSIA-D0N: CON1.11(MDN0_B) D3.4(IN3) D3.7(OUT3) ; off-sheet MCSIA-D0N
MCSIA-D0P: CON1.12(MDP0_B) D3.5(IN4) D3.6(OUT4) ; off-sheet MCSIA-D0P
MCSIA-D1N: CON1.8(MDN1_B) D3.1(IN1) D3.10(OUT1) ; off-sheet MCSIA-D1N
MCSIA-D1P: CON1.9(MDP1_B) D3.2(IN2) D3.9(OUT2) ; off-sheet MCSIA-D1P
MCSIA-D2N: CON1.5(MDN2_B) D4.4(IN3) D4.7(OUT3) ; off-sheet MCSIA-D2N
MCSIA-D2P: CON1.6(MDP2_B) D4.5(IN4) D4.6(OUT4) ; off-sheet MCSIA-D2P
MCSIA-D3N: CON1.2(MDN3_B) D4.1(IN1) D4.10(OUT1) ; off-sheet MCSIA-D3N
MCSIA-D3P: CON1.3(MDP3_B) D4.2(IN2) D4.9(OUT2) ; off-sheet MCSIA-D3P
MCSIC-CKN: CON1.23(MCN_F) D6.4(IN3) D6.7(OUT3) ; off-sheet MCSIC-CKN
MCSIC-CKP: CON1.24(MCP_F) D6.5(IN4) D6.6(OUT4) ; off-sheet MCSIC-CKP
MCSIC-D0N: CON1.20(MDN0_F) D6.1(IN1) D6.10(OUT1) ; off-sheet MCSIC-D0N
MCSIC-D0P: CON1.21(MDP0_F) D6.2(IN2) D6.9(OUT2) ; off-sheet MCSIC-D0P
MCSIC-D1N: CON1.17(MDN1_F) D5.4(IN3) D5.7(OUT3) ; off-sheet MCSIC-D1N
MCSIC-D1P: CON1.18(MDP1_F) D5.5(IN4) D5.6(OUT4) ; off-sheet MCSIC-D1P

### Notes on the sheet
- Camera
- 注意：
  MCSIA和 MCSIB、MCSIC 和 MCSID 才能组合成 4line 使用，MCSIA 和
  MCSIB 用作 4line 时，需使用 MCSIA
  的 CLK，MCSIB 的 CLK 可以悬空，也可以用作普通 IO，其中
  MCSIA0、MCSIA1、MCSIB0、MCSIB1
  依次对应 MCSI0/1/2/3；MCSIC 和 MCSID 用作 4line 时，需使用
  MCSIC 的 CLK，MCSID 的 CLK
  可以悬空，也可以用作普通 IO，其中
  MCSIC0、MCSIC1、MCSID0、MCSID1 依次对应 MCSI0/1/2/3
  Attention:
  MCSIA and MCSIB, MCSIC and MCSID can be combined to form 4line
  When MCSIA and MCSIB are used as 4Lines,
  use MCSIA
  The CLK of MCSIB can be suspended or used as normal
  IO, where MCSIA0, MCSIA1, MCSIB0, and MCSIB1 are displayed
  Corresponding to MCSI0/1/2/3;
  MCSIC and MCSID are used as 4lines
  ", the CLK of MCSIC and CLK of MCSID are required
  Can be suspended, can also be used as ordinary IO,where
  MCSIC0, MCSIC1, MCSID0, and MCSID1 correspond in sequence
  MCSI0/1/2/3
- (near CP4) 1.8V

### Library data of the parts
CON1 = CON39PIN_0
CP1-CP4 = C-C0603-X5R_1: Parameter: C0402-X5R
D3-D8 = rRClamp0524P
D9-D12 = 1_1.5KE100A_Dup1: as D61 on sheet 11 OTG_host_HUB
R15 R16 = R-R0402-1%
